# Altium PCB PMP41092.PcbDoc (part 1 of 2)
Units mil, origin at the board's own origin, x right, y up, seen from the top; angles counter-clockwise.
Board outline 1771.65 x 1771.65 mil, 6 copper layers (Top Layer 1, Layer 2, Layer 3, Layer 4, Layer 5, Bottom Layer), stack 32.112 mil thick; 119 components, 63 nets, 374 pads, 304 vias.
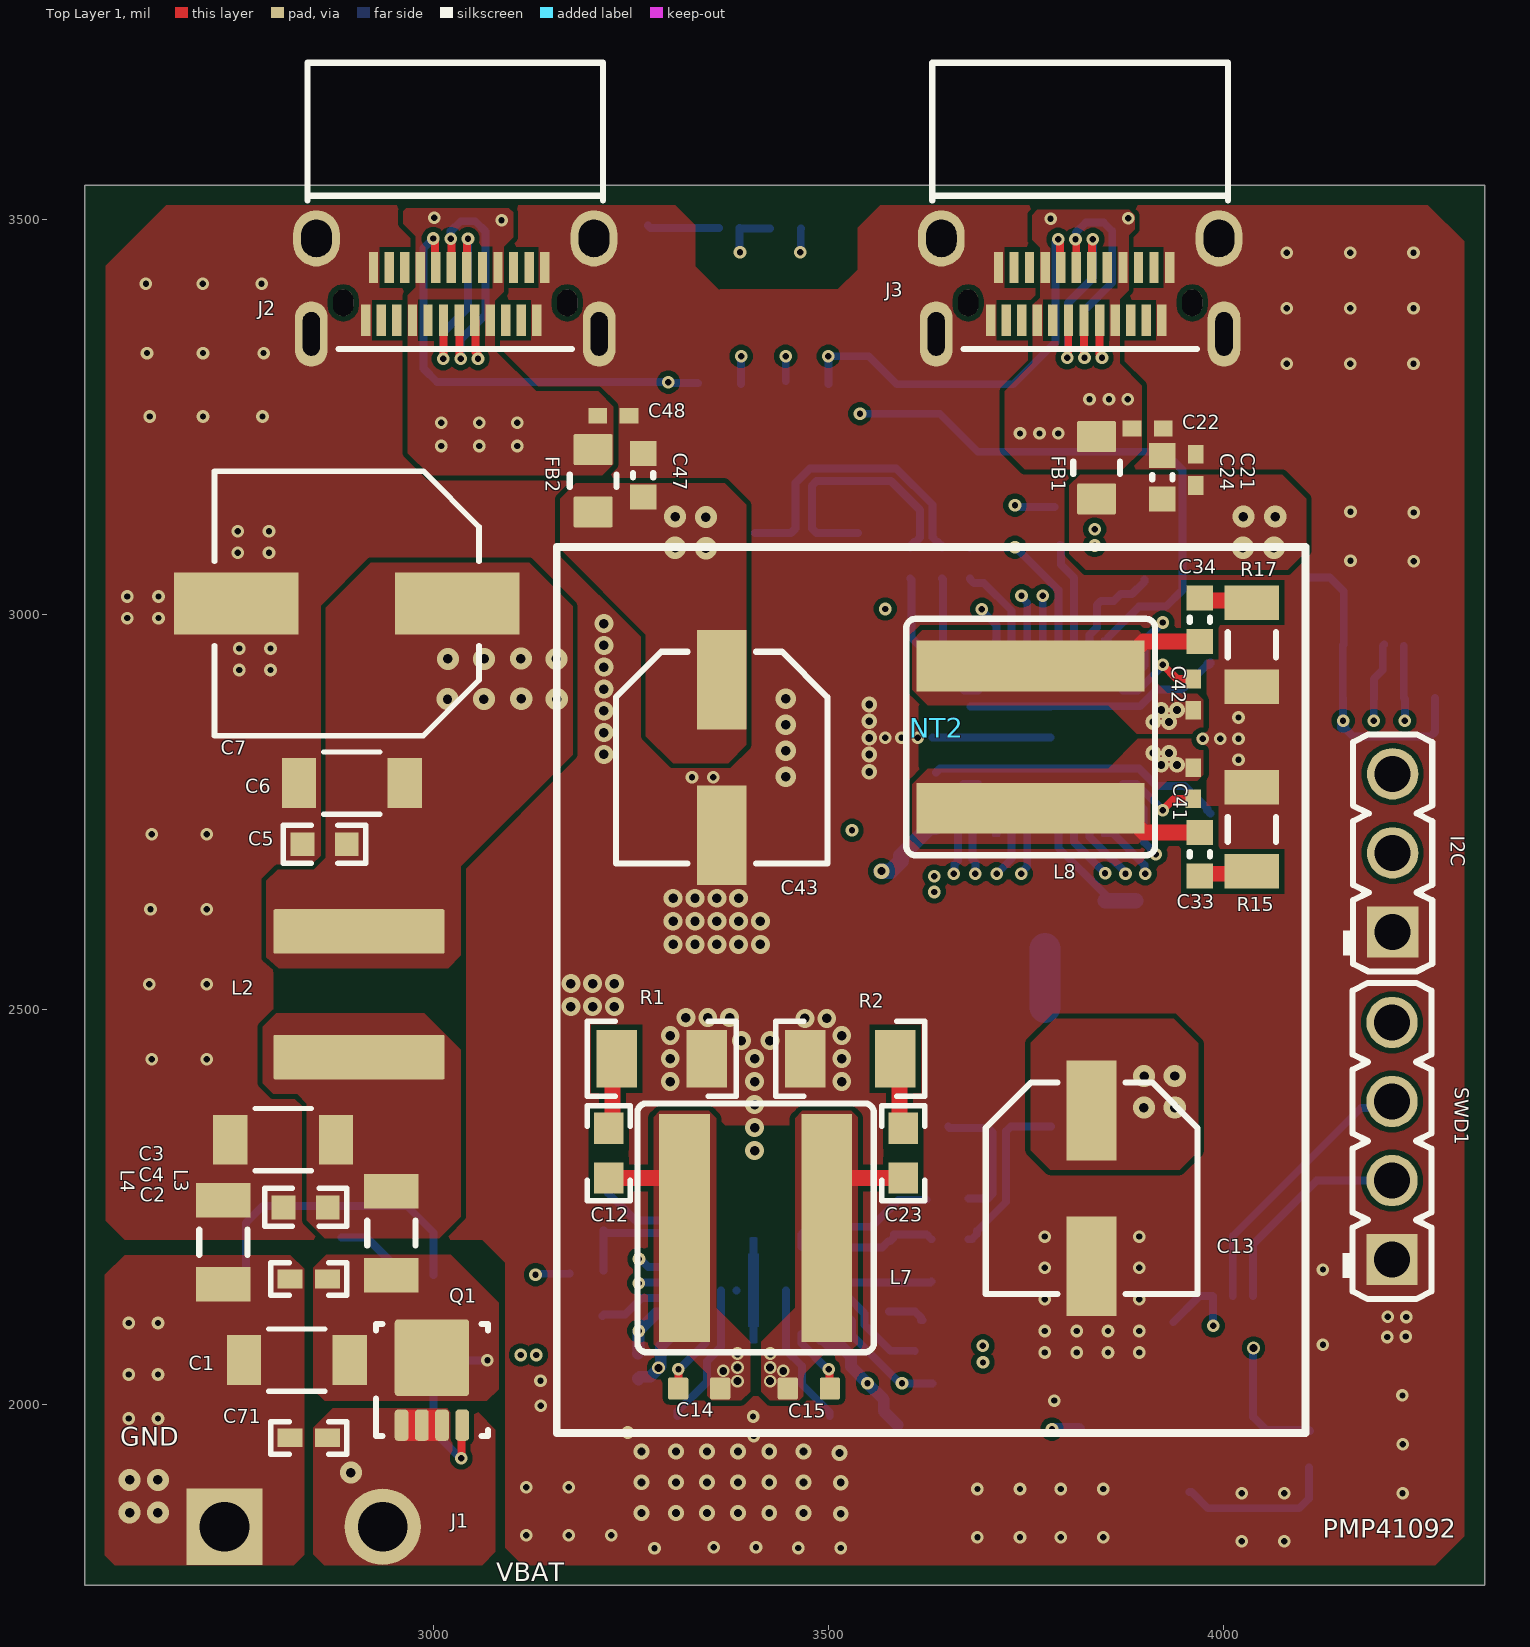
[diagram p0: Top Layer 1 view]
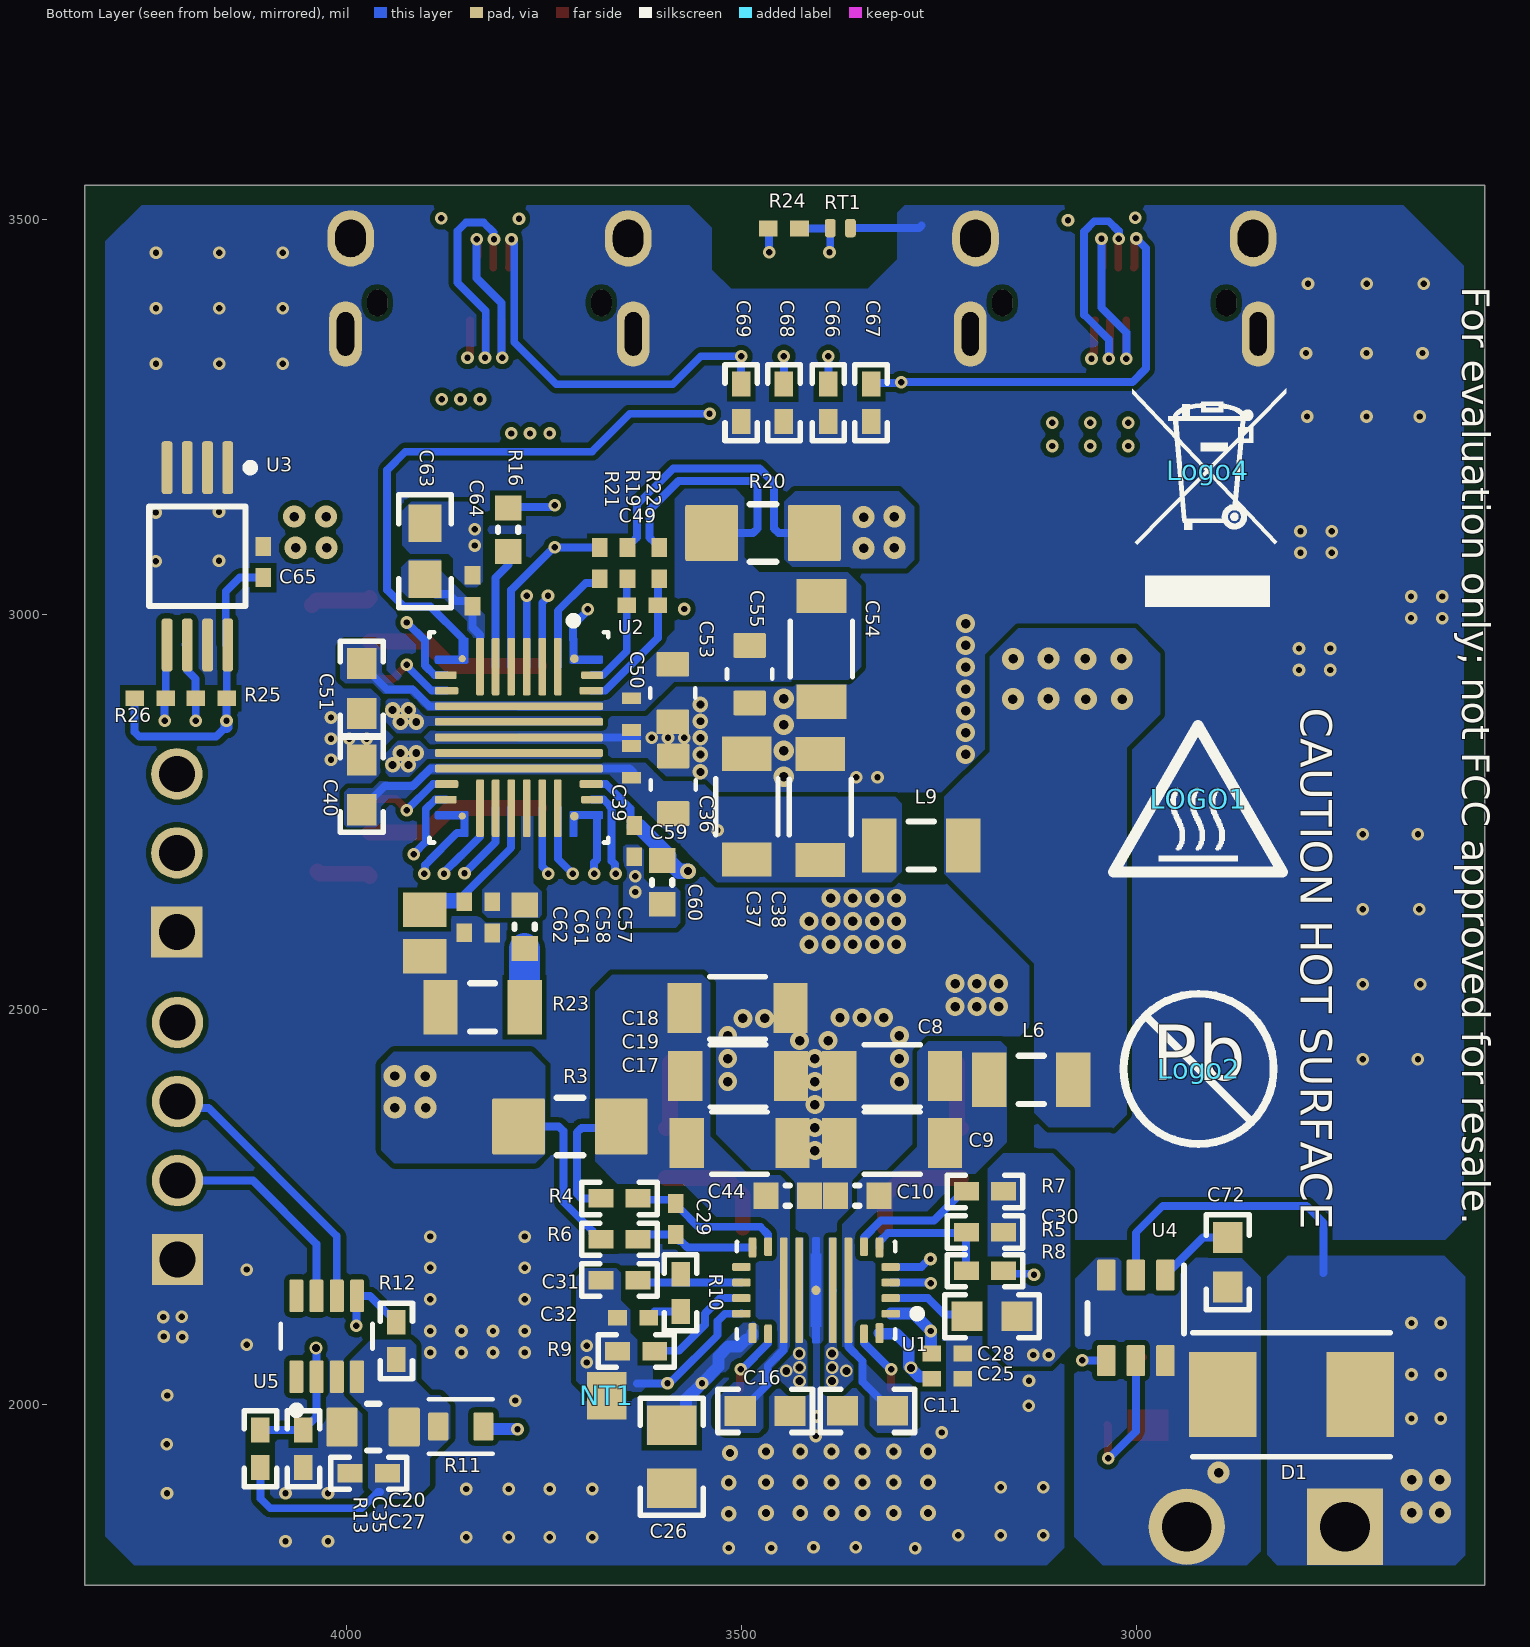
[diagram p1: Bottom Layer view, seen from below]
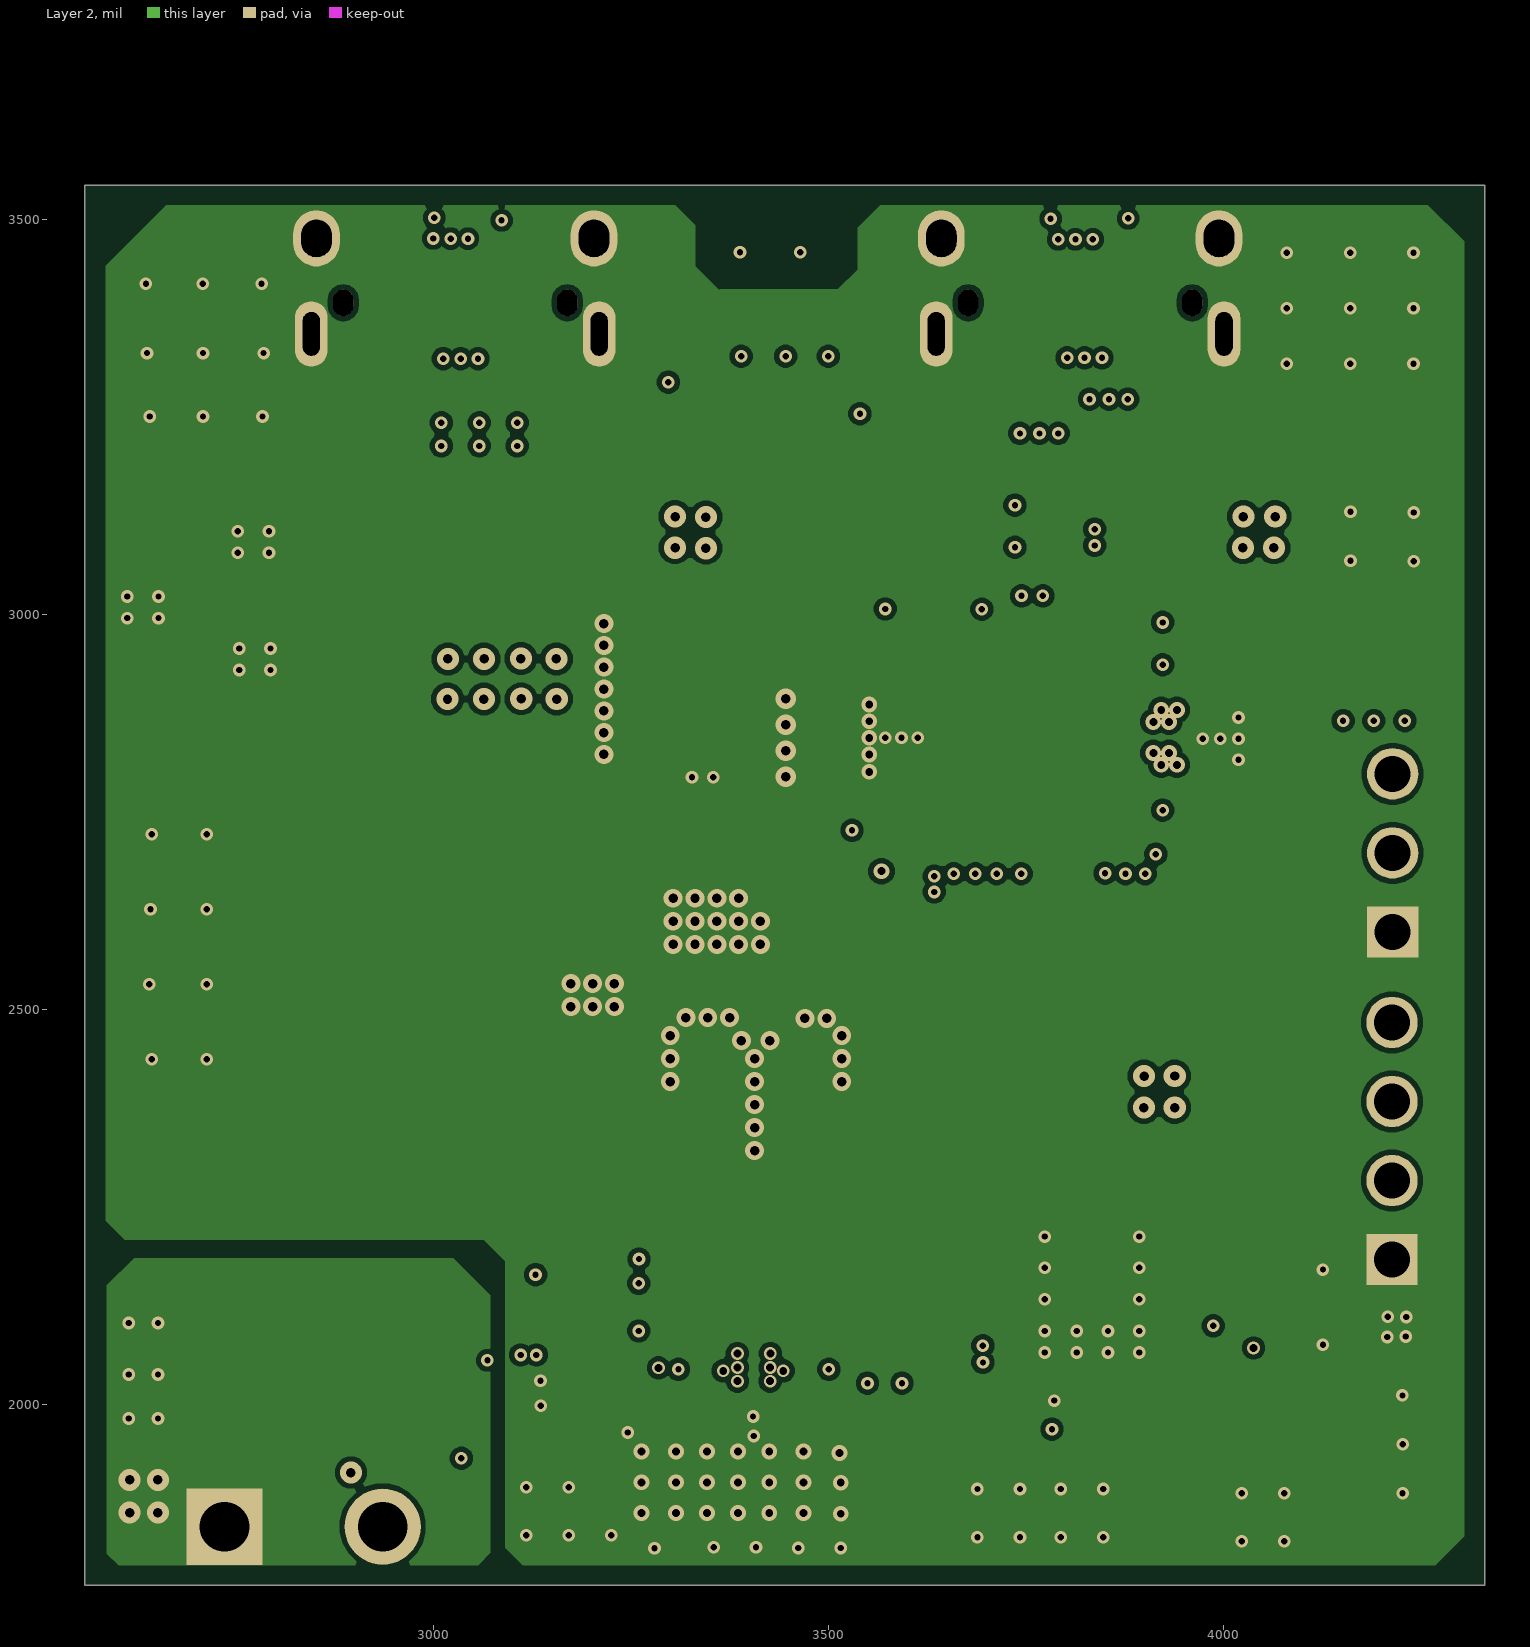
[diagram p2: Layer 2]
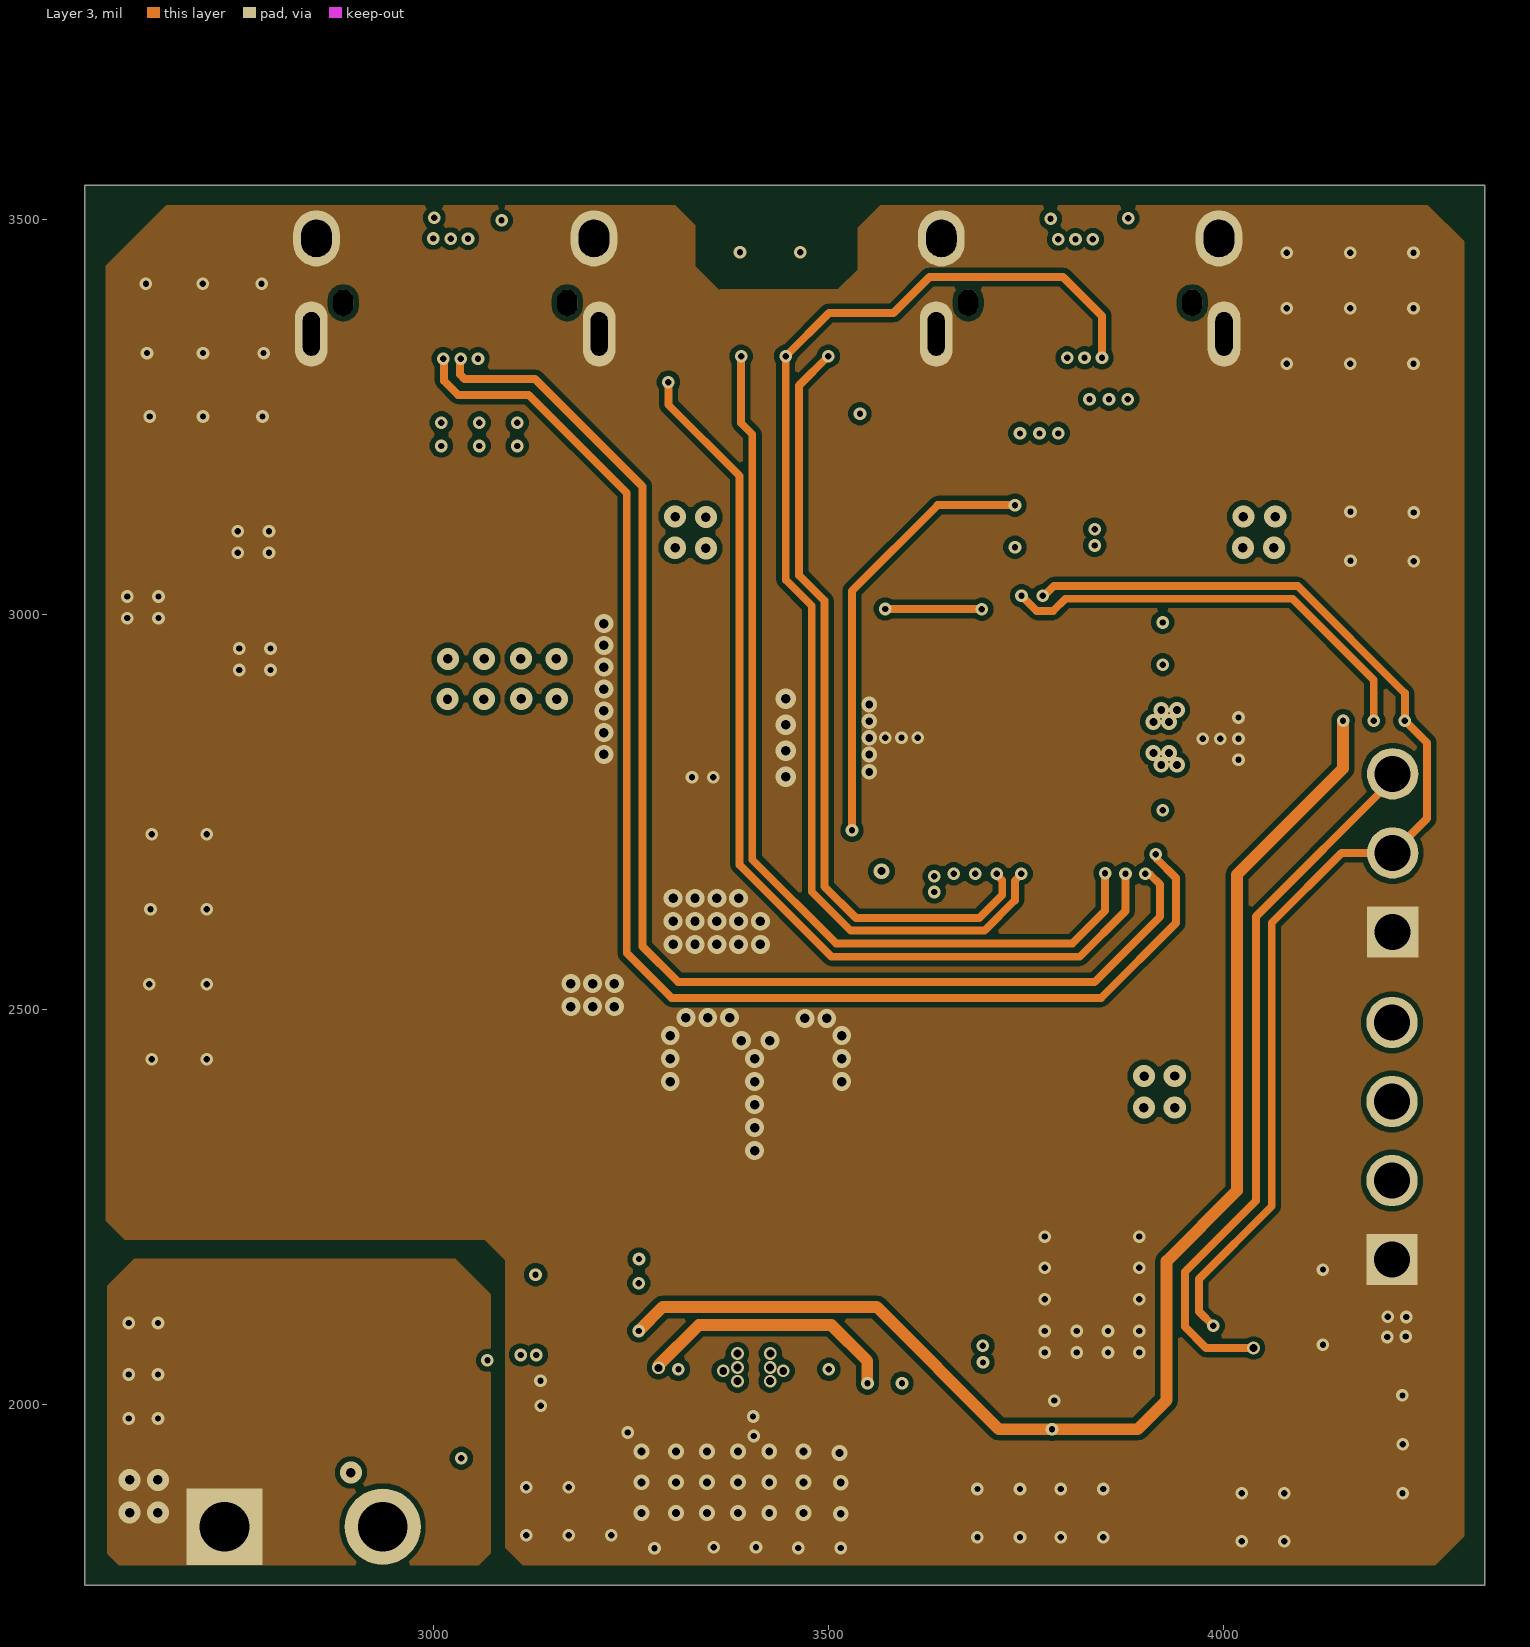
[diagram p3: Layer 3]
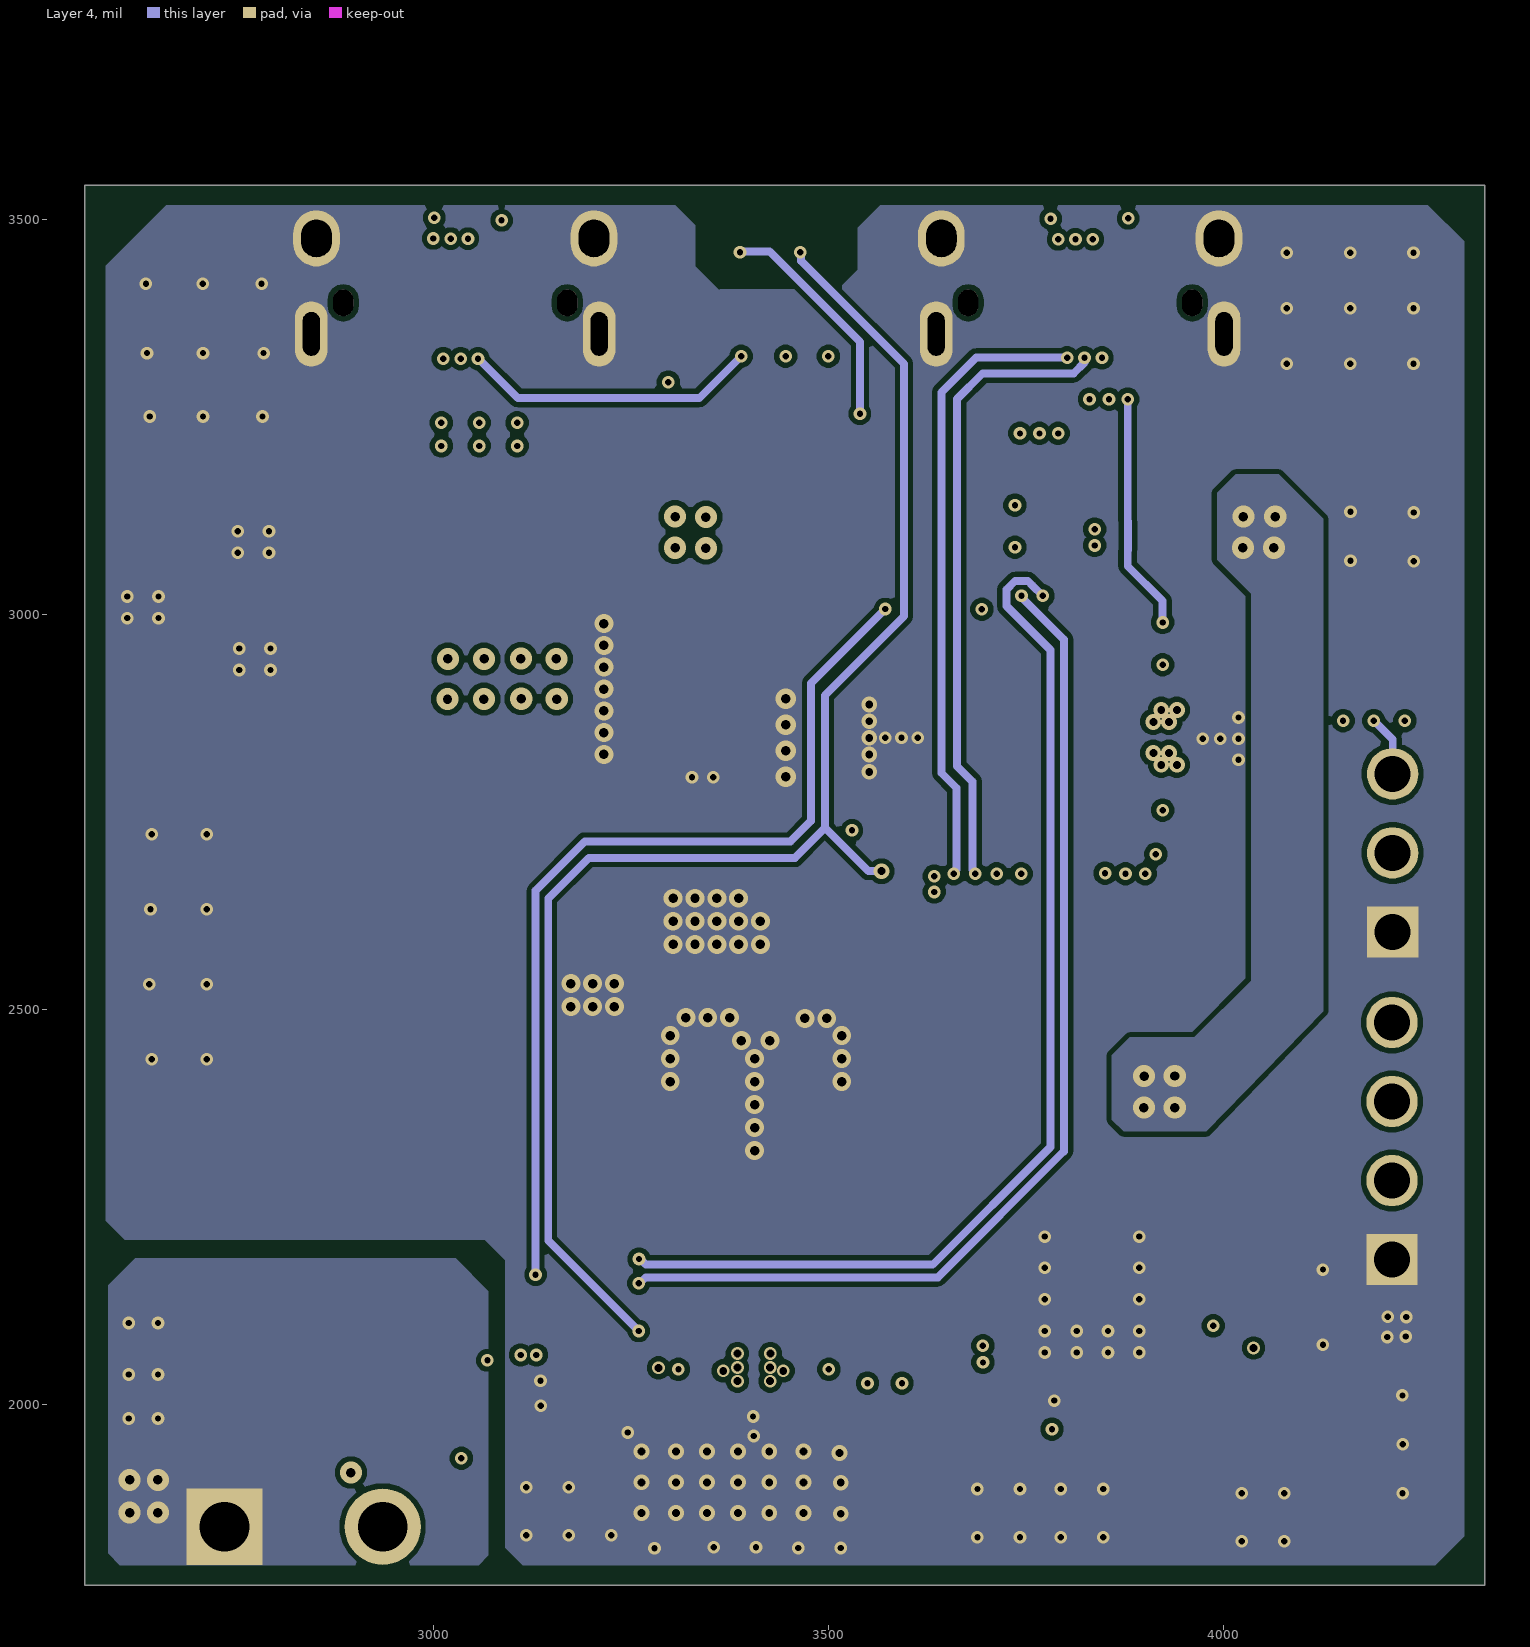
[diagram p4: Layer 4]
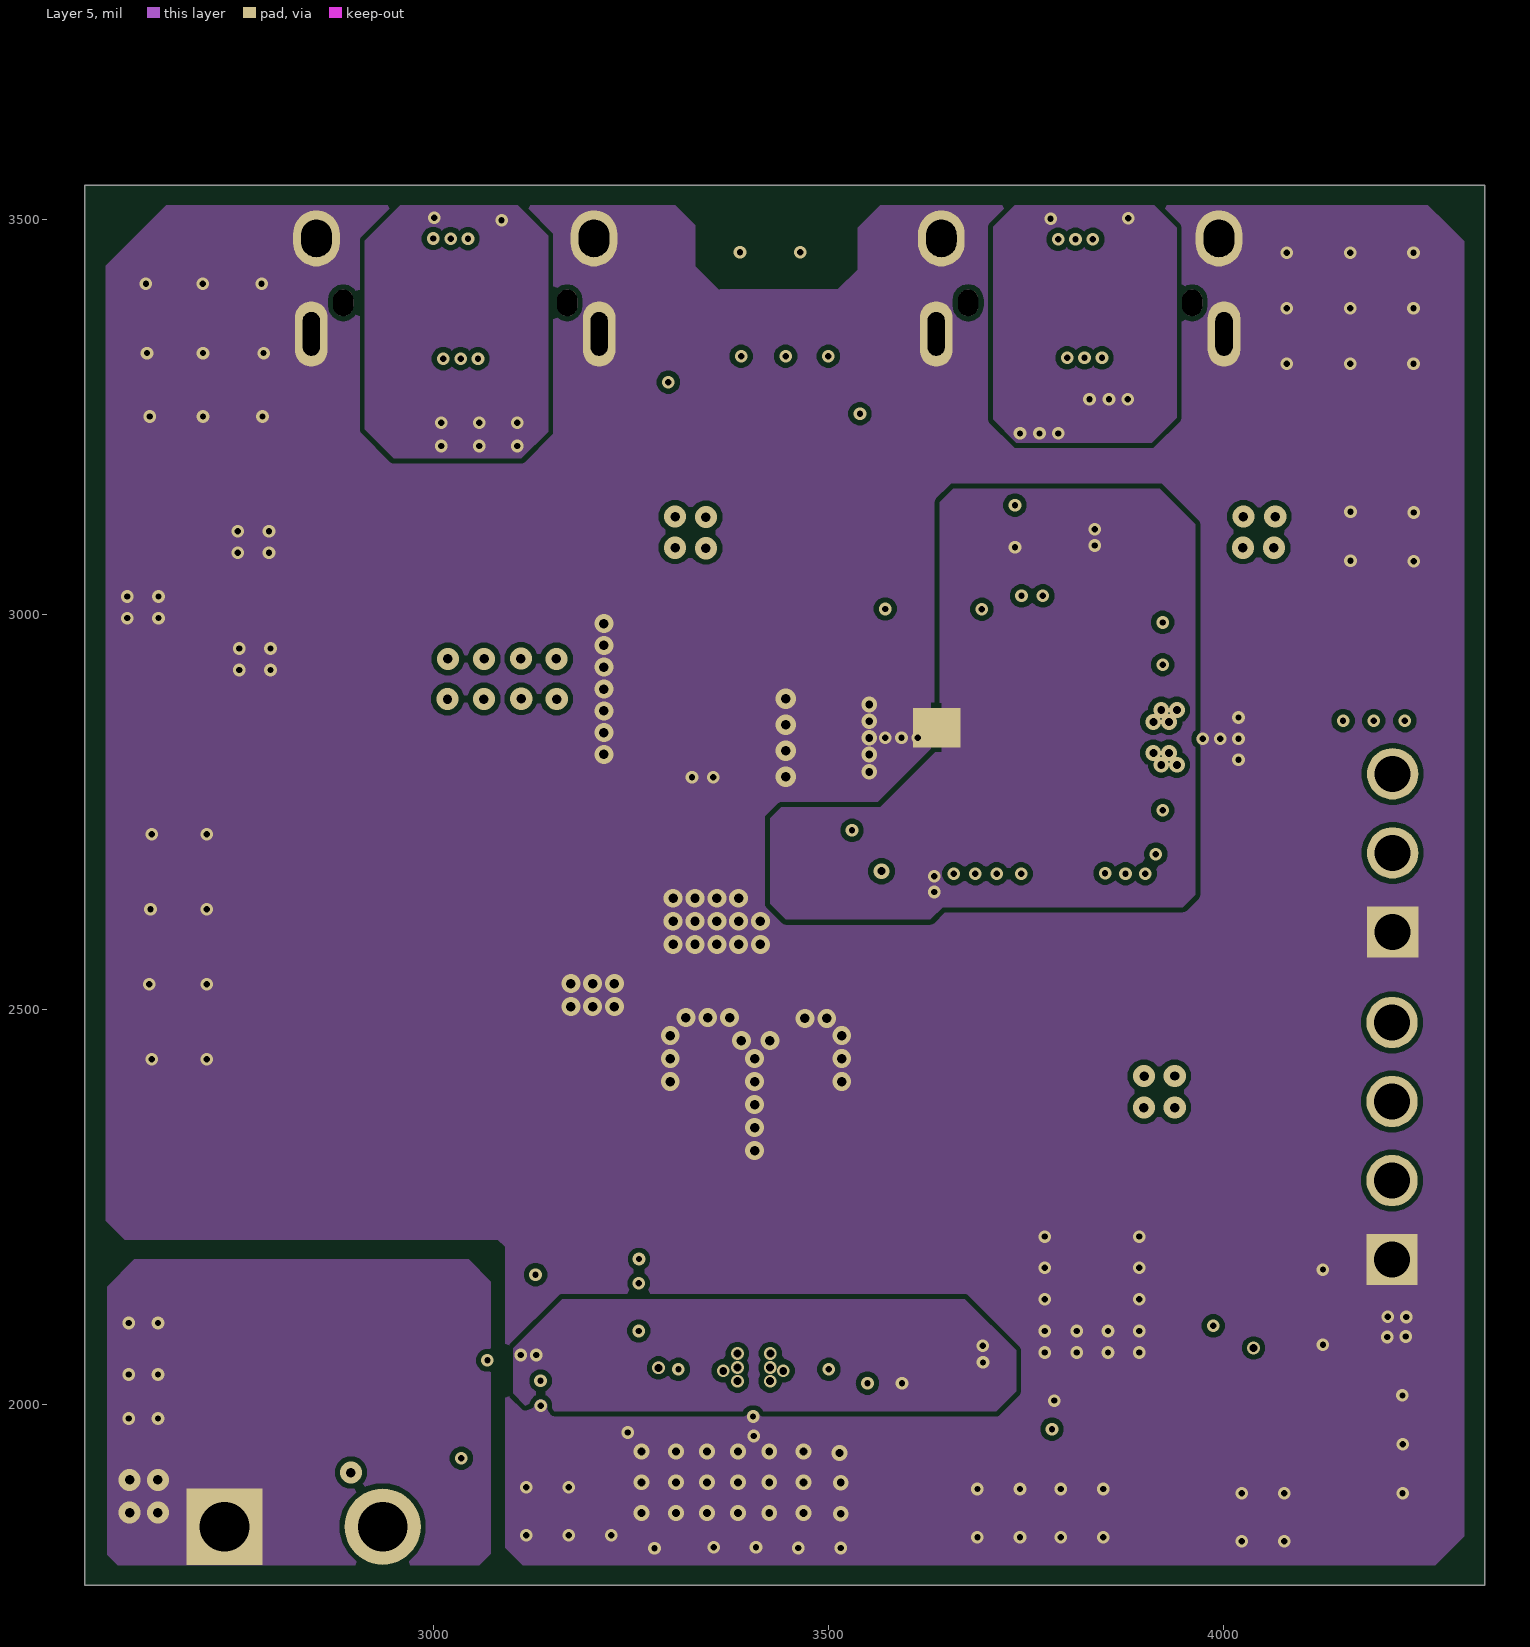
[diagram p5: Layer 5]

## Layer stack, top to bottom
Top Solder: solder mask 0.4, Solder Resist, Dk 3.5
Top Layer 1: signal copper 1.378
Dielectric 2: prepreg 2.8, PP-006, Dk 4.1
Layer 2: signal copper 1.4
Dielectric 4: prepreg 2.8, PP-006, Dk 4.1
Layer 3: signal copper 1.378
Dielectric 1: dielectric 12.6, FR-4, Dk 4.8
Layer 4: signal copper 1.378
Dielectric 5: prepreg 2.8, PP-006, Dk 4.1
Layer 5: signal copper 1.4
Dielectric 3: prepreg 2.8, PP-006, Dk 4.1
Bottom Layer: signal copper 1.378
Bottom Solder: solder mask 0.4, Solder Resist, Dk 3.5

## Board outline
2559.06,1771.65 4330.71,1771.65 4330.71,3543.31 2559.06,3543.31

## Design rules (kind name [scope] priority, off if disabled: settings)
AcuteAngle [All] p1: minimum=4.50000000000000E+0001 checktracksonly=FALSE
AssemblyTestPointUsage [All] p1: valid=2
BoardOutlineClearance BoardOutlineClearance_MountingHoles [OnCopper and InComponentClass('Mounting Holes')] p1: gap=10 ignorepadtopadclearanceinfootprint=FALSE
BoardOutlineClearance BoardOutlineClearance_Poly [OnCopper and IsPoly] p2: gap=25 ignorepadtopadclearanceinfootprint=FALSE
BoardOutlineClearance [OnCopper and Not InComponentClass('Logo') and not InComponentClass('FiducialMark') and not InRegion(1000,500,4000,800) and not InPoly] p3: gap=10 ignorepadtopadclearanceinfootprint=FALSE
Clearance Clearance_Keepouts [((IsTrack Or IsArc) And Not InPoly) And IsFree and IsKeepOut vs ((IsTrack Or IsArc) And Not InPoly) And IsFree and IsKeepOut] p1: gap=0 ignorepadtopadclearanceinfootprint=FALSE
Clearance Clearance_Poly [InPolygon] p2: gap=6.5 ignorepadtopadclearanceinfootprint=TRUE
Clearance Clearance_FiducialMark [IsKeepOut and InComponentClass('FiducialMark') vs IsPad and InComponentClass('FiducialMark')] p3: gap=0 ignorepadtopadclearanceinfootprint=FALSE
Clearance [All] p4: gap=6 ignorepadtopadclearanceinfootprint=TRUE
ComponentClearance ComponentClearance_MountingHoles_FiducialMarks [InComponentClass('Mounting Holes') vs InComponentClass('FiducialMark')] p1: gap=5 collisioncheckmode=3 verticalgap=3 showdistances=FALSE
ComponentClearance ComponentClearance_Shunt [InComponentClass('Header') vs InComponentClass('Shunt')] p2: gap=0 collisioncheckmode=3 verticalgap=0 showdistances=FALSE
ComponentClearance ComponentClearance_Logo [InComponentClass('Logo')] p3: gap=10 collisioncheckmode=3 verticalgap=10 showdistances=FALSE
ComponentClearance ComponentClearance_ScrewToNut [(HasFootprint('NY PMS 440 0025 PH')) vs (HasFootprint('Keystone_1902C'))] p4: gap=5 collisioncheckmode=3 verticalgap=10 showdistances=FALSE
ComponentClearance ComponentClearance_MountingHoles [InComponentClass('Mounting Holes')] p5: gap=50 collisioncheckmode=3 verticalgap=100000 showdistances=FALSE
ComponentClearance ComponentClearance_SmallPassives [HasFootprint('0201*') or HasFootprint('0402*') or HasFootprint('0508') or HasFootprint('0603*') or HasFootprint('0612') or HasFootprint('0805*') or HasFootprint('0815*') or HasFootprint('0830*') or HasFootprint('1206*') or HasFootprint('1210*') or HasFootprint('1808*') or HasFootprint('1812*') or HasFootprint('1825*') or HasFootprint('2010*') or HasFootprint('2220*') or HasFootprint('2225*') or HasFootprint('2512*') or HasFootprint('2728*') or HasFootprint('3518*') vs HasFootprint('0201*') or HasFootprint('0402*') or HasFootprint('0508') or HasFootprint('0603*') or HasFootprint('0612') or HasFootprint('0805*') or HasFootprint('0815*') or HasFootprint('0830*') or HasFootprint('1206*') or HasFootprint('1210*') or HasFootprint('1808*') or HasFootprint('1812*') or HasFootprint('1825*') or HasFootprint('2010*') or HasFootprint('2220*') or HasFootprint('2225*') or HasFootprint('2512*') or HasFootprint('2728*') or HasFootprint('3518*')] p6: gap=0 collisioncheckmode=3 verticalgap=0 showdistances=FALSE
ComponentClearance ComponentClearance_THtoSMT [IsThruComponent vs IsSMTComponent] p7: gap=2 collisioncheckmode=3 verticalgap=2 showdistances=FALSE
ComponentClearance ComponentClearance_THtoTH [IsThruComponent vs IsThruComponent] p8: gap=5 collisioncheckmode=3 verticalgap=5 showdistances=FALSE
ComponentClearance [All] p9: gap=0 collisioncheckmode=3 verticalgap=0 showdistances=FALSE
DiffPairsRouting [All] p1: maxlimit=15 minlimit=6 mostfreqgap=10 toplayer_minwidth=6 toplayer_maxwidth=15 toplayer_prefwidth=10 midlayer1_minwidth=6 midlayer1_maxwidth=15 midlayer1_prefwidth=10 midlayer2_minwidth=6 midlayer2_maxwidth=15 midlayer2_prefwidth=10 midlayer3_minwidth=6 midlayer3_maxwidth=15 midlayer3_prefwidth=10 midlayer4_minwidth=6 midlayer4_maxwidth=15 midlayer4_prefwidth=10 bottomlayer_minwidth=6 bottomlayer_maxwidth=15 bottomlayer_prefwidth=10 maxuncoupledlength=20
FabricationTestPointUsage TestPointUsage [All] p1: valid=2 allowmultiple=FALSE
FabricationTestpoint Testpoint [All] p1: side=3 testpointundercomponent=TRUE minsize=40 maxsize=100 preferedsize=60 minholesize=0 maxholesize=40 preferedholesize=32 testpointgrid=1 allowsidetop=TRUE allowsidebottom=TRUE usegrid=TRUE gridtolerance=0.01
FanoutControl Fanout_LCC [IsLCC] p1: bgadir=Out bgaviamode=Centered fanoutstyle=Auto fanoutdirection=Alternating viagrid=1 // Fanout_LCC (Default Rule)
FanoutControl Fanout_BGA [IsBGA] p2: bgadir=Out bgaviamode=Centered fanoutstyle=Auto fanoutdirection=Alternating viagrid=1 // Fanout_BGA (Default Rule)
FanoutControl Fanout_Default [All] p4: bgadir=Out bgaviamode=Centered fanoutstyle=Auto fanoutdirection=Alternating viagrid=1 // Fanout_Default (Default Rule)
FanoutControl Fanout_Small [(CompPinCount < 5)] p5: bgadir=Out bgaviamode=Centered fanoutstyle=Auto fanoutdirection=OutThenIn viagrid=1 // Fanout_Small (Default Rule)
HoleSize [All] p1: absolutevalues=TRUE maxlimit=300 minlimit=5 maxpercent=80.000 minpercent=20.000
HoleToHoleClearance [All] p1: gap=0 allowstackedmicrovias=TRUE
MatchedLengths DiffPair_MatchedLengths [InDifferentialPair ('PA_D')] p1: tolerance=1000 checknetsindiffpair=FALSE checkdiffpairvsdiffpair=TRUE checkxsignals=TRUE checkothers=TRUE
MatchedLengths [InDifferentialPair ('PA_D')] p2: tolerance=1000 checknetsindiffpair=FALSE checkdiffpairvsdiffpair=TRUE checkxsignals=TRUE checkothers=TRUE
MinimumAnnularRing MinimumAnnularRing_ThermalPadVias [IsVia and InAnyComponent] p1: minimumring=1.5
MinimumAnnularRing [All] p2: minimumring=1.5
MinimumSolderMaskSliver MinimumSolderMaskSliver_Logo [InComponentClass('Logo') vs InComponentClass('Logo')] p1: minsoldermaskwidth=0.7
MinimumSolderMaskSliver [All] p2: minsoldermaskwidth=0
PlaneConnect [All] p1: planeconnectstyle=Direct reliefexpansion=10 reliefentries=4 reliefconductorwidth=10 reliefairgap=10
PolygonConnect [All] p1: connectstyle=Direct reliefconductorwidth=10 reliefentries=4 polygonreliefangle="90 Angle" airgapwidth=10
RoomDefinition PMP41092_TPS55289 [InComponentClass('PMP41092_TPS55289')] p1: confinementstyle=ConfineIn formatcopy=TRUE lockcomponents=FALSE outline 0,0 2000,0 2000,1000 0,1000
RoomDefinition PMP41092_TPS25772 [InComponentClass('PMP41092_TPS25772')] p2: confinementstyle=ConfineIn formatcopy=TRUE lockcomponents=FALSE outline 0,0 2000,0 2000,1000 0,1000
RoomDefinition "PMP41092_Input filter" [InComponentClass('PMP41092_Input filter')] p3: confinementstyle=ConfineIn formatcopy=TRUE lockcomponents=FALSE outline 0,0 2000,0 2000,1000 0,1000
RoutingLayers [All] p1: top layer_v5=TRUE mid layer 1_v5=TRUE mid layer 2_v5=TRUE mid layer 3_v5=FALSE mid layer 4_v5=FALSE bottom layer_v5=TRUE
RoutingVias ThermalPadVias [IsVia and InAnyComponent] p1: holewidth=50 width=50 viastyle="Through Hole" minholewidth=5 minwidth=10 maxholewidth=100 maxwidth=200
RoutingVias [All] p2: holewidth=10 width=16 viastyle="Through Hole" minholewidth=6 minwidth=10 maxholewidth=100 maxwidth=300
ShortCircuit [All vs InNet('No Net')] p1: allowed=FALSE
SilkToSilkClearance SilkToSilkClearance_Pb-FreeLogo [(HasFootprint('Pb-Free_Overlay_Medium') OR HasFootprint('Pb-Free_Overlay_Small')) vs (HasFootprint('Pb-Free_Overlay_Medium') OR HasFootprint('Pb-Free_Overlay_Small'))] p1: silktosilkclearance=0
SilkToSilkClearance [All] p2: silktosilkclearance=0
SilkToSolderMaskClearance SilkToComponentPadClearance [(IsPad or IsFill or IsRegion) and InAnycomponent] p1: minsilkscreentomaskgap=0 clearancetoexposedcopper=TRUE
SilkToSolderMaskClearance "Silk to Solder Mask Opening" [All] p2: minsilkscreentomaskgap=0 clearancetoexposedcopper=FALSE
SolderMaskExpansion [All] p1: expansion=1.97 istentingtop=FALSE
UnRoutedNet [All] p1: checkbadconnections=TRUE
Width [All] p1: maxlimit=100 minlimit=6 preferedwidth=10 checkconnectedcopper=TRUE
12 further rules are at their usual default settings.

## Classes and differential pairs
component class PMP41092_TPS55289: C8 C9 C10 C11 C12 C13 C14 C15 C16 C17 C18 C19 C21 C22 C23 C24 C25 C26 C28 C29 C30 C31 C32 C44 FB1 L6 L7 LOGO1 Logo2 Logo3 Logo4 NT1 R1 R2 R3 R4 R5 R6 R7 R8 R9 R10 U1
component class PMP41092_TPS25772: C20 C27 C33 C34 C35 C36 C37 C38 C39 C40 C41 C42 C43 C47 C48 C49 C50 C51 C53 C54 C55 C57 C58 C59 C60 C61 C62 C63 C64 C65 C66 C67 C68 C69 FB2 I2C J2 J3 L8 L9 NT2 R11 R12 R13 R15 R16 R17 R19 R20 R21 R22 R23 R24 R25 R26 RT1 SWD1 U2 U3 U5 x
component class "PMP41092_Input filter": C1 C2 C3 C4 C5 C6 C7 C71 C72 D1 J1 L2 L3 L4 Q1 SH1 U4
differential pair PB_D: +PB_D_P -PB_D_N
differential pair PA_D: +PA_D_P -PA_D_N

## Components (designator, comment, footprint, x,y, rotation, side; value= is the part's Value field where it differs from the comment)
C1 "GRT31CD71H106KE13" 1206_190 2827.55,2056.62 r180 top value=10uF
C2 "Capacitor" 0402 2842.74,2159.27 r180 top value=0.1uF
C3 "CGA5L3X7R1H475K160AE" 1206_190 2810.31,2335.55 r180 top value=4.7uF
C4 "GRT155R71H472KE01" 0603_HV 2838.74,2249.83 r180 top value=4700pF
C5 "GRT155R71H472KE01" 0603_HV 2862.62,2709.18 r180 top value=4700pF
C6 "CGA5L3X7R1H475K160AE" 1206_190 2897.08,2786.73 r180 top value=4.7uF
C7 "EEE-FK1H101P" SM_RADIAL_F 2890.68,3014.01 r180 top value=100uF
C8 "CGA5L1X7R1H106K160AC" 1206_190 3308.91,2416.23 r0 bottom value=10uF
C9 "CGA5L1X7R1H106K160AC" 1206_190 3308.91,2331.18 r0 bottom value=10uF
C10 "CGA3E3X5R1H105M080AB" 0603L 3353.2,2264.69 r0 bottom value=1uF
C11 "GCM188R71H104KA57D" 0603 3340.11,1992.32 r0 bottom value=0.1uF
C12 "GRM1885C1H222JA01D" 0603 3222,2318.5 r270 top value=2200pF
C13 "GRM1885C1H222JA01D" 0603 3595,2318.5 r90 top value=2200pF
C14 "GCM188L81H104KA57D" FP-GCM188L81H104KA57D_0603-MFG 3336.59,2020.61 r0 top
C15 "GCM188L81H104KA57D" FP-GCM188L81H104KA57D_0603-MFG 3475.37,2020.61 r180 top
C16 "GCM188R71H104KA57D" 0603 3469.77,1992.26 r180 bottom value=0.1uF
C17 "GRT31CD71H106KE13" 1206_190 3502.09,2331.18 r180 bottom value=10uF
C18 "GRT31CD71H106KE13" 1206_190 3504.68,2502.14 r180 bottom value=10uF
C19 "GRT31CD71H106KE13" 1206_190 3504.01,2416.23 r180 bottom value=10uF
C20 "GCJ21BR71A106KE01L" 0805_HV1 3965.71,1971.87 r0 bottom value=10uF
C21 "Capacitor" 0402L 3964.88,3183 r90 top value=0.1uF
C22 "Capacitor" 0402L 3903.93,3235.36 r0 top value=0.1uF
C23 "EEHZK1V101XP" Panasonic_D 3833.12,2274.08 r270 top value=100uF
C24 "CGA3E3X5R1H105M080AB" 0603L 3922.58,3173.76 r90 top value=1uF
C25 "Capacitor" 0402L 3239.32,2033.17 r180 bottom value=0.1uF
C26 "GCM21BR71C475KA73K" 0805_HV 3587.9,1934.35 r270 bottom value=4.7uF
C27 "GRT155R71H104KE01" 0402 3971.13,1913.49 r180 bottom value=0.1uF
C28 "Capacitor" 0402L 3239.32,2065 r180 bottom value=0.1uF
C29 "CGA2B1X7R1V224K050BC" 0402L 3582.76,2235.16 r90 bottom value=0.22uF
C30 "CGA2B3X7R1H103K050BB" 0402 3191.52,2218.56 r180 bottom value=0.01uF
C31 "Capacitor" 0402 3653.97,2157.81 r0 bottom value=100pF
C32 "GCM155R71H472KA37D" 0402L 3636.81,2110.46 r0 bottom value=4700pF
C33 "GCM1885C1H102JA16D" 0603L 3970,2696.69 r270 top value=1000pF
C34 "GRM188R71H332KA01D" 0603L 3970,2993.31 r90 top value=3300pF
C35 "CGA2B3X7R1H103K050BB" 0402 4054.01,1944.52 r270 bottom value=0.01uF
C36 "GRT21BC71H475KE13" FP-CGA4J1X7R1H475K125AC_0805-MFG 3586,2784.58 r270 bottom value=4.7µF
C37 "GRT31CD71H106KE13" 1206_190 3492.89,2756.8 r90 bottom value=10uF
C38 "GRT31CD71H106KE13" 1206_190 3399.97,2756.51 r90 bottom value=10uF
C39 "GRT155R71H104KE01" 0402S 3639,2813.49 r270 bottom value=0.1uF
C40 "GCM188R71H104KA57D" 0603 3979.93,2784.54 r90 bottom value=0.1uF
C41 "GRT155R71H104KE01" 0402L 3961.99,2786.46 r90 top value=0.1uF
C42 "GRT155R71H104KE01" 0402L 3961.99,2898.69 r270 top value=0.1uF
C43 "EEHZK1V101XP" Panasonic_D 3365.05,2818.98 r270 top value=100uF
C44 "GCM188R71H104KA57D" 0603L 3441.31,2264.69 r180 bottom value=0.1uF
C47 "CGA3E3X5R1H105M080AB" 0603L 3265.82,3176.21 r90 top value=1uF
C48 "GRT155R71H104KE01" 0402L 3228.06,3251.38 r180 top value=0.1uF
C49 "CGA2B1X7R1V224K050BC" 0402L 3625.17,3011.76 r0 bottom value=0.22uF
C50 "GRT155R71H104KE01" 0402S 3639,2874 r90 bottom value=0.1uF
C51 "GCM188R71H104KA57D" 0603 3980,2906.5 r270 bottom value=0.1uF
C53 "GRT21BC71H475KE13" FP-CGA4J1X7R1H475K125AC_0805-MFG 3586.63,2900.72 r90 bottom value=4.7µF
C54 "GRT31CD71H106KE13" 1206_190 3398.58,2956.48 r270 bottom value=10uF
C55 "GRT21BC71H475KE13" FP-CGA4J1X7R1H475K125AC_0805-MFG 3489.35,2924.48 r90 bottom value=4.7µF
C57 "CGA3E3X7R1H474K080AE" 0603L 3774.02,2604.92 r270 bottom value=0.47uF
C58 "GRT155R71H104KE01" 0402L 3814.98,2616.73 r90 bottom value=0.1uF
C59 "GRT155R71C104KE01" 0402L 3635.11,2713.31 r270 bottom value=0.1uF
C60 "GRT188D70J106ME13D" 0603L 3600,2661 r270 bottom value=10uF
C61 "GRT155R71C104KE01" 0402L 3850.16,2617.08 r270 bottom value=0.1uF
C62 "GCM21BR71C475KA73K" 0805L 3900.61,2597.04 r270 bottom value=4.7uF
C63 "GRT188D70J106ME13D" 0603M 3900,3080 r90 bottom value=10uF
C64 "GRT155R71C104KE01" 0402L 3840,3030 r90 bottom value=0.1uF
C65 "GRT155R71H104KE01" 0402L 4104.8,3066.45 r270 bottom value=0.1uF
C66 "GRT155R71H331KE01" 0402 3389.89,3267.92 r270 bottom value=330pF
C67 "GRT155R71H331KE01" 0402 3335.66,3267.92 r270 bottom value=330pF
C68 "GRT155R71H331KE01" 0402 3446.08,3267.92 r270 bottom value=330pF
C69 "GRT155R71H331KE01" 0402 3500,3267.92 r270 bottom value=330pF
C71 "GRM155R71H104ME14D" 0402 2842.74,1958.25 r180 top value=0.1uF
C72 "GRM188R71E105KA12D" 0603 2884.24,2180.42 r270 bottom value=1uF
D1 "P6SMB33CA" SMB-Bi 2803.81,2013.05 r0 bottom value=28.2V
FB1 "BLM21SP700SZ1D" 0805_HV1 3839.37,3185.64 r90 top
FB2 "BLM21SP700SZ1D" 0805_HV1 3202.41,3169.24 r90 top
I2C "61300311121" WURTH_61300311121 4214,2698.35 r90 top
J1 "691313510002" FP-691313510002_TRM_BLK_HDR2-MFG 2836.16,1688.45 r0 top
J2 "632722200212" 632722200212 3027.91,3511.26 r180 top
J3 "632722200212" 632722200212 3818.6,3511.26 r180 top
L2 "XAL6060-472MEB" XAL6060 2906.3,2519.45 r90 top value=4.7uH
L3 "BLM31SN500SZ1L" 1206L 2947.25,2217.26 r90 top value="50 ohm"
L4 "BLM31SN500SZ1L" 1206L 2734.63,2205.82 r90 top value="50 ohm"
L6 "BLM31SN500SZ1L" 1206L 3133.08,2411.35 r0 bottom value="50 ohm"
L7 "XAL7070-472MEB" XAL7070 3408,2224 r0 top value=4.7uH
L8 "XAL7070-472MEB" XAL7070 3756,2845 r90 top value=4.7uH
L9 "BLM31SN500SZ1L" 1206L 3272.17,2707.78 r0 bottom value="50 ohm"
LOGO1 "CAUTION HOT SURFACE" IEC_HotSurface_Small 2922,2767 r180 bottom
Logo2 "Pb-Free Symbol" Pb-Free_Overlay_Medium 2921.26,2425.2 r180 bottom
Logo3 "FCC disclaimer" FCC_disclaimer 4657.47,2377.95 r90 bottom
Logo4 "WEEE logo" WEEE_Minimum 2910,3182 r180 bottom
NT1 "Net-Tie" Net-Tie_50milWide_30milLong#1 3670.01,2011.42 r270 bottom net-tie
NT2 "Net-Tie" Net-Tie_50milWide_30milLong#2 3637,2857 r0 top net-tie
Q1 "IPZ40N04S5L-2R8" PG-TSDSON-8-32 2998.45,2031.38 r90 top value=40V
R1 "Resistor" 1206 3289.29,2438 r0 top value=2.20
R2 "Resistor" 1206 3527.71,2438 r180 top value=2.20
R3 "CRF1206-FZ-R010ELF" FP-CRF1206-FZ-R010ELF_1206-MFG 3716.67,2352.25 r0 bottom
R4 "CRCW040210R0FKED" 0402 3653.97,2261.23 r180 bottom value=10.0
R5 "RK73Z1ETTP" 0402 3191.52,2169.68 r180 bottom value=0
R6 "CRCW040210R0FKED" 0402 3653.97,2209.56 r180 bottom value=10.0
R7 "Resistor" 0402 3191.52,2270.21 r0 bottom value=49.9k
R8 "ERJ-3GEY0R00V" 0603 3182.72,2112.29 r180 bottom value=0
R9 "Resistor" 0402 3633,2068 r180 bottom value=150k
R10 "CRCW040227K4FKED" 0402 3576.68,2141.72 r90 bottom value=27.4k
R11 "ERJ-3GEY0R00V" FP-ERJ-3GEY0R00V_0603-MFG 3854.74,1972.62 r0 bottom
R12 "RK73H1ETTP3301F" 0402 3936.37,2080.87 r270 bottom value=3.30k
R13 "RK73H1ETTP3301F" 0402 4108.41,1944.52 r270 bottom value=3.30k
R15 "CRCW12061R10FKEA" 1206L 4036,2728.19 r270 top value=1.10
R16 "CRCW060347K0FKEA" 0603L 3794.92,3107.26 r90 bottom value=47.0k
R17 "CRCW12061R10FKEA" 1206L 4036,2961.81 r270 top value=1.10
R19 "CRCW04020000Z0EDHP" 0402L 3643.84,3065.01 r90 bottom value=0
R20 "CRF1206-FZ-R010ELF" FP-CRF1206-FZ-R010ELF_1206-MFG 3472.41,3103.1 r180 bottom
R21 "CRCW040210R0FKED" 0402L 3603.71,3065.01 r90 bottom value=10.0
R22 "ERJ-2GEJ103X" 0402L 3679.22,3065.01 r270 bottom value=10k
R23 "RC1206FR-0710RL" 1206L 3827.15,2503 r180 bottom value=10.0
R24 "ERJ-2GEJ103X" 0402L 3445.94,3488.4 r0 bottom value=10k
R25 "RK73H1ETTP3301F" 0402L 4170.57,2893.91 r180 bottom value=3.30k
R26 "RK73H1ETTP3301F" 0402L 4247.79,2894.27 r0 bottom value=3.30k
RT1 "TMP6131QDECRQ1" DEC0002A 3374.56,3488.94 r0 bottom
SWD1 "61300411121" WURTH_61300411121 4213.24,2333.87 r90 top
U1 "TPS55289QWRYQRQ1" RYQ0021B-MFG 3405.33,2144.97 r0 bottom
U2 "TPS25772CQRQLRQ1" RQL0029A-MFG 3781.2,2844.51 r270 bottom
U3 "24LC256-I/ST" TSSOP-8 4188.05,3073.64 r270 bottom
U4 "LM74700QDBVRQ1" DBV0006A_N 3000.68,2110.07 r270 bottom
U5 "MSPM0C1104" DDF0008A-MFG 4024.49,2086.7 r90 bottom

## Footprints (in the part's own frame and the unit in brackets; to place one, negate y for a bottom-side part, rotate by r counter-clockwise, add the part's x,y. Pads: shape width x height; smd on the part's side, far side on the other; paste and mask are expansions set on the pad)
0402 [mm] "0402 from SM-752 data"
  rect 0.8x0.6 smd: 1(-0.6,0) 2(0.6,0)
  silkscreen extent -1.22,-0.52 1.22,0.52, body extent -0.55,-0.3 0.55,0.3, height 0.6
0402L [mm] "0402 from SM-752 data"
  rect 0.6x0.5 smd: 1(-0.5,0) 2(0.5,0)
  body extent -0.55,-0.3 0.55,0.3, height 0.6
0402S [mil] "Based on C0402S footprint from PADS legacy"
  rect 15x24 smd: 1(-20,0) 2(20,0)
  body extent -22,-12 22,12, height 24
0603 [mm] "0603 from SM-752 data"
  rect 1x0.95 smd: 1(-0.8,0) 2(0.8,0)
  silkscreen extent -1.52,-0.69 1.52,0.69, body extent -0.87,-0.47 0.87,0.47, height 1
0603_HV [mil] "Ernesto recommended land pattern.  26 mil between pads."
  rect 30x30 smd: 1(-28,0) 2(28,0)
  silkscreen extent -52,-24 52,24, body extent -34,-19 34,19, height 39
0603L [mm] "0603 from SM-752 data"
  rect 0.8x0.85 smd: 1(-0.7,0) 2(0.7,0)
  silkscreen extent -0.07,-0.33 0.07,0.33, body extent -0.87,-0.47 0.87,0.47, height 1
0603M [mm] "0603 from SM-752 data"
  rect 1.2x1.05 smd: 1(-0.9,0) 2(0.9,0)
  silkscreen extent -1.82,-0.84 1.82,0.84, body extent -0.87,-0.47 0.87,0.47, height 1
0805_HV [mil] "0805 with 30mil clearance between pads"
  rect 50x63 smd: 1(-40,0) 2(40,0)
  silkscreen extent -74,-40 74,40, body extent -43,-29 43,29, height 57
0805_HV1 [mm] "Custom footprint based on analyzing multiple manufacturer recommendations"
  rrect10% 1x1.25 smd: 1(-1,0) 2(1,0)
  silkscreen extent -0.2,-0.75 0.2,0.75, body extent -1.1,-0.72 1.1,0.73, height 1.45
0805L [mm] "0805 from SM-752 data"
  rect 1.1x1.4 smd: 1(-0.75,0) 2(0.75,0)
  body extent -1.1,-0.72 1.1,0.72, height 1.45
1206 [mm] "1206 from SM-752 data"
  rect 1.3x1.85 smd: 1(-1.45,0) 2(1.45,0)
  silkscreen extent -2.4,-1.21 2.4,1.21, body extent -1.7,-0.9 1.7,0.9, height 1.35
1206_190 [mm] "1206_190"
  rect 1.1x1.6 smd: 1(-1.7,0) 2(1.7,0)
  silkscreen extent -0.9,-1 0.9,1, body extent -1.75,-0.95 1.75,0.95, height 1.9
1206L [mm] "1206 from SM-752 data"
  rect 1.1x1.75 smd: 1(-1.35,0) 2(1.35,0)
  silkscreen extent -0.4,-0.77 0.4,0.77, body extent -1.7,-0.9 1.7,0.9, height 1.35
632722200212 [mm] "USB 3.1 Horizontal Receptacle SMT"
  rect 0.3x1 smd: A1(-2.625,3.53) A2(-2.125,3.53) A3(-1.625,3.53) A4(-1.125,3.53) A5(-0.625,3.53) A6(-0.125,3.53) A7(0.375,3.53) A8(0.875,3.53) A9(1.375,3.53) A10(1.875,3.53) A11(2.375,3.53) A12(2.875,3.53) B1(2.625,1.83) B2(2.125,1.83) B3(1.625,1.83) B4(1.125,1.83) B5(0.625,1.83) B6(0.125,1.83) B7(-0.375,1.83) B8(-0.875,1.83) B9(-1.375,1.83) B10(-1.875,1.83) B11(-2.375,1.83) B12(-2.875,1.83)
  oval 0.65x0.85 hole 0.65 slot 0.85 at 90 deg unplated: M1(-3.6,2.97) M2(3.6,2.97)
  oval 1.05x2.1 hole 0.55 slot 1.4 at 90 deg: Shell(-4.625,3.97) Shell(4.625,3.97)
  oval 1.5x1.8 hole 0.98 slot 1.2 at 90 deg: Shell(-4.46,0.9) Shell(4.46,0.9)
  silkscreen extent -4.75,-4.75 4.75,4.45, body extent -4.76,-4.75 4.75,4.45, height 5.51
DBV0006A_N [mm] "SOT23, 6-Leads, Body 2.9x1.6mm, Pitch 0.95mm, Lead Span 2.8mm, IPC Medium Density"
  rrect17% 1x0.6 smd: 1(-1.375,0.95) 2(-1.375,0) 3(-1.375,-0.95) 4(1.375,-0.95) 5(1.375,0) 6(1.375,0.95)
  silkscreen extent -1.68,-1.55 0.5,1.55, body extent -1.42,-1.46 1.42,1.46, height 1.12
DDF0008A-MFG [mm]
  rrect22% 1.05x0.45 smd paste+0 mask+0: 1(-1.3,0.975) 2(-1.3,0.325) 3(-1.3,-0.325) 4(-1.3,-0.975) 5(1.3,-0.975) 6(1.3,-0.325) 7(1.3,0.325) 8(1.3,0.975)
  silkscreen extent -2.5,-1.48 0.4,1.48, body extent -1.41,-1.45 1.41,1.45, height 1.1
DEC0002A [mm] "X1SON-2"
  rrect57% 0.35x0.6 smd paste-0.5 mask-0.05: 1(-0.325,0) 2(0.325,0)
  rrect33% 0.3x0.5 on Bottom Paste: 1S(-0.35,0) 2S(0.35,0)
  body extent -0.5,-0.3 0.5,0.3, height 0.5
FCC_disclaimer [mil]
FP-691313510002_TRM_BLK_HDR2-MFG [mm]
  rect 2.45x2.45 hole 1.6 paste-1000 mask+0: 1(-2.54,4)
  round 2.45 hole 1.6 paste-1000 mask+0: 2(2.54,4)
  body extent -6.25,-6.2 6.25,6.2, height 0.25
FP-CGA4J1X7R1H475K125AC_0805-MFG [mm]
  rrect13% 0.8x1.05 smd paste+0 mask+0: 1(-0.925,0) 2(0.925,0)
  silkscreen extent -0.15,-0.72 0.15,0.72, body extent -1,-0.63 1,0.63, height 1.45
FP-CRF1206-FZ-R010ELF_1206-MFG [mm]
  rrect6% 1.7x1.8 smd paste+0 mask+0: 1(-1.65,0) 2(1.65,0)
  silkscreen extent -0.43,-0.92 0.43,0.92, body extent -1.6,-0.82 1.6,0.82, height 0.8
FP-ERJ-3GEY0R00V_0603-MFG [mm]
  rrect15% 0.65x0.9 smd paste+0 mask+0: 1(-0.725,0) 2(0.725,0)
  silkscreen extent -1.03,-0.87 1.03,0.87, body extent -0.8,-0.4 0.8,0.4, height 0.55
FP-GCM188L81H104KA57D_0603-MFG [mm]
  rrect15% 0.65x0.7 smd paste+0 mask+0: 1(-0.675,0) 2(0.675,0)
  body extent -0.8,-0.4 0.8,0.4, height 0.9
IEC_HotSurface_Small [mil]
  silkscreen extent -107,-93 107,92
Net-Tie_50milWide_30milLong#1 [mil] "50mil net tie, no solder mask opening, no solder paste"
  rect 30x50 smd paste-20 mask-20: 1(-15,0) 2(15,0)
Net-Tie_50milWide_30milLong#2 [mil] "50mil net tie, no solder mask opening, no solder paste"
  rect 30x50 on Mid1 paste-20 mask-20: 1(-15,0) 2(15,0)
Panasonic_D [mm] "SMD, 2-Leads, Dia 6.3mm"
  rect 3.2x1.6 smd: 1(-2.5,0) 2(2.5,0)
  silkscreen extent -3.4,-3.4 3.4,3.4, body extent -3.4,-3.4 3.4,3.4, height 6.11
Pb-Free_Overlay_Medium [mil]
  silkscreen extent -95,-95 95,95
PG-TSDSON-8-32 [mm] "SMD, 8-Leads, Body 3.3x3.3mm"
  rrect45% 1x0.44 smd paste-1 mask-0.05: 1(-1.45,0.975) 2(-1.45,0.325) 3(-1.45,-0.325) 4(-1.45,-0.975) 5(1.45,-0.975) 6(1.45,-0.325) 7(1.45,0.325) 8(1.45,0.975)
  rrect6% 1.71x2.29 on Top Solder: 9(0.395,0)
  rrect8% 2.46x2.39 smd paste-2 mask-2: 9(0.72,0)
  rrect42% 0.3x0.24 on Top Paste: ""(-1.695,-0.325) ""(-1.695,0.325) ""(-1.695,0.975)
  rrect42% 0.7x0.24 on Top Paste: ""(-1.5,-0.975)
  rrect29% 0.35x0.67 on Top Paste: ""(-1.225,0.76) ""(-1.22,-0.11)
  rrect42% 1.4x0.24 on Top Paste: ""(0.35,0.975) ""(0.35,-0.975)
  rrect9% 1.4x1.09 on Top Paste: ""(0.35,0)
  rrect42% 0.6x0.24 on Top Paste: ""(1.55,-0.975) ""(1.55,-0.325) ""(1.55,0.325) ""(1.55,0.975)
  Top Layer 1 region: -1.95,-0.325 -0.95,-0.325 -0.95,1 -1.95,1
  silkscreen extent -1.8,-1.8 1.8,1.8, body extent -1.7,-1.7 1.7,1.7, height 1.15
RQL0029A-MFG [mm]
  round 0.278 smd paste+0 mask+0: 1(-2.53,1.78) 25(2.53,1.78)
  rrect40% 1.85x0.25 smd paste-1000 mask+0: 2(-2.275,1.25) 3(-2.275,0.75) 4(-2.275,0.25) 5(-2.275,-0.25) 6(-2.275,-0.75) 7(-2.275,-1.25) 19(2.275,-1.25) 20(2.275,-0.75) 21(2.275,-0.25) 22(2.275,0.25) 23(2.275,0.75) 24(2.275,1.25)
  round 0.229 smd paste+0 mask+0: 8(-2.53,-1.823) 18(2.53,-1.823)
  rrect40% 0.25x0.7 smd paste+0 mask+0: 9(-2,-2.35) 17(2,-2.35) 26(2,2.35) 29(-2,2.35)
  rrect40% 0.25x0.75 smd paste+0 mask+0: 10(-1.5,-2.325) 16(1.5,-2.325) 27(1.5,2.325) 28(-1.5,2.325)
  rrect40% 0.25x5.4 smd paste-1000 mask+0: 11(-1,0) 12(-0.5,0) 13(0,0) 14(0.5,0) 15(1,0)
  Top Layer 1 region: -2.425,-2.7 -2.575,-2.7 -2.594,-2.696 -2.61,-2.685 -2.621,-2.669 -2.625,-2.65 -2.625,-2.65 -2.625,-1.925 -2.629,-1.906 -2.64,-1.89 -2.656,-1.879 -2.675,-1.875 -2.675,-1.875 -3.15,-1.875 -3.175,-1.868 -3.193,-1.85 -3.2,-1.825 -3.2,-1.825 -3.2,-1.675 -3.196,-1.656 -3.185,-1.64 -3.169,-1.629 -3.15,-1.625 -3.15,-1.625 -2.425,-1.625 -2.406,-1.629 -2.39,-1.64 -2.379,-1.656 -2.375,-1.675 -2.375,-1.675 -2.375,-2.65 -2.379,-2.669 -2.39,-2.685 -2.406,-2.696 -2.425,-2.7
  Top Layer 1 region: 2.425,-2.7 2.575,-2.7 2.594,-2.696 2.61,-2.685 2.621,-2.669 2.625,-2.65 2.625,-2.65 2.625,-1.925 2.629,-1.906 2.64,-1.89 2.656,-1.879 2.675,-1.875 2.675,-1.875 3.15,-1.875 3.175,-1.868 3.193,-1.85 3.2,-1.825 3.2,-1.825 3.2,-1.675 3.196,-1.656 3.185,-1.64 3.169,-1.629 3.15,-1.625 3.15,-1.625 2.425,-1.625 2.406,-1.629 2.39,-1.64 2.379,-1.656 2.375,-1.675 2.375,-1.675 2.375,-2.65 2.379,-2.669 2.39,-2.685 2.406,-2.696 2.425,-2.7
  Top Layer 1 region: 2.425,2.7 2.575,2.7 2.594,2.696 2.61,2.685 2.621,2.669 2.625,2.65 2.625,2.65 2.625,1.925 2.629,1.906 2.64,1.89 2.656,1.879 2.675,1.875 2.675,1.875 3.15,1.875 3.175,1.868 3.193,1.85 3.2,1.825 3.2,1.825 3.2,1.675 3.196,1.656 3.185,1.64 3.169,1.629 3.15,1.625 3.15,1.625 2.425,1.625 2.406,1.629 2.39,1.64 2.379,1.656 2.375,1.675 2.375,1.675 2.375,2.65 2.379,2.669 2.39,2.685 2.406,2.696 2.425,2.7
  Top Layer 1 region: -2.425,2.7 -2.575,2.7 -2.594,2.696 -2.61,2.685 -2.621,2.669 -2.625,2.65 -2.625,2.65 -2.625,1.925 -2.629,1.906 -2.64,1.89 -2.656,1.879 -2.675,1.875 -2.675,1.875 -3.15,1.875 -3.169,1.871 -3.185,1.86 -3.196,1.844 -3.2,1.825 -3.2,1.825 -3.2,1.675 -3.196,1.656 -3.185,1.64 -3.169,1.629 -3.15,1.625 -3.15,1.625 -2.425,1.625 -2.406,1.629 -2.39,1.64 -2.379,1.656 -2.375,1.675 -2.375,1.675 -2.375,2.65 -2.379,2.669 -2.39,2.685 -2.406,2.696 -2.425,2.7
  silkscreen extent -3.87,-2.88 3.37,2.88, body extent -3,-2.5 3,2.5, height 1
RYQ0021B-MFG [mm]
  rrect40% 0.6x0.25 smd paste+0 mask+0: 1(-2.4,0.75) 2(-2.4,0.25) 3(-2.4,-0.25) 4(-2.4,-0.75) 14(2.4,-0.75) 15(2.4,-0.25) 16(2.4,0.25) 17(2.4,0.75)
  rrect40% 0.25x0.65 smd paste+0 mask+0: 5(-2.04,-1.375) 13(2.04,-1.375) 18(2.04,1.375) 21(-2.04,1.375)
  rrect40% 0.25x0.6 smd paste+0 mask+0: 6(-1.54,-1.4) 12(1.54,-1.4) 19(1.54,1.4) 20(-1.54,1.4)
  rrect40% 0.25x3.4 smd paste-1000 mask+0: 7(-1.04,0) 8(-0.54,0) 10(0.54,0) 11(1.04,0)
  round 0.297 smd paste-1000 mask+0: 9(0,0)
  Top Layer 1 region: -0.125,-1.65 -0.125,-1.175 -0.165,-1.175 -0.165,1.175 -0.125,1.175 -0.125,1.65 -0.118,1.675 -0.1,1.693 -0.075,1.7 -0.075,1.7 0.075,1.7 0.1,1.693 0.118,1.675 0.125,1.65 0.125,1.65 0.125,1.175 0.165,1.175 0.165,-1.175 0.125,-1.175 0.125,-1.65 0.118,-1.675 0.1,-1.693 0.075,-1.7 0.075,-1.7 -0.075,-1.7 -0.1,-1.693 -0.118,-1.675 -0.125,-1.65 -0.125,-1.65
  silkscreen extent -3.37,-1.55 2.55,1.55, body extent -2.5,-1.5 2.5,1.5, height 1
SM_RADIAL_F [mm] "8 x 10.2mm:  Panasonic F"
  rect 4x2 smd: 1(-3.55,0) 2(3.55,0)
  silkscreen extent -4.25,-4.25 4.25,4.25, body extent -4.25,-4.25 4.25,4.25, height 10.5
SMB-Bi [mil] "Molded Diode, 2-Leads, Body 5.4x3.6mm, IPC Medium Density, based on OnSemi component dimensions"
  rect 85x107.99 smd: 1(-87.01,0) 2(87.01,0)
  silkscreen extent -125,-79 125,79, body extent -104,-73 104,73, height 89
TSSOP-8 [mm] "TSSOP, 8-Leads, Body 3.1x4.5mm (max), Pitch 0.65mm, IPC Medium Density"
  rrect50% 1.7x0.35 smd: 1(-2.85,0.975) 2(-2.85,0.325) 3(-2.85,-0.325) 4(-2.85,-0.975) 5(2.85,-0.975) 6(2.85,-0.325) 7(2.85,0.325) 8(2.85,0.975)
  silkscreen extent -2.97,-1.55 1.6,1.82, body extent -3.2,-1.55 3.2,1.55, height 1.07
WEEE_Minimum [mil] "WEEElie bin"
  silkscreen extent -95,-172 99,104
WURTH_61300311121 [mm] "Header, 2.54mm, 3x1, TH"
  rect 1.65x1.65 hole 1.15: 1(-2.54,0)
  round 1.65 hole 1.15: 2(0,0) 3(2.54,0)
  silkscreen extent -3.81,-1.27 3.81,1.6, body extent -3.81,-1.27 3.81,1.27, height 8.54
WURTH_61300411121 [mm] "Header, 2.54mm, 4x1, TH"
  rect 1.65x1.65 hole 1.15: 1(-3.81,0)
  round 1.65 hole 1.15: 2(-1.27,0) 3(1.27,0) 4(3.81,0)
  silkscreen extent -5.08,-1.27 5.08,1.6, body extent -5.08,-1.27 5.08,1.27, height 8.54
XAL6060 [mm] "Coilcraft recommended land pattern Document 887-4 Revised 01/14/18"
  rrect7% 1.43x5.5 smd: 1(-2.019,0) 2(2.019,0)
  body extent -3.28,-3.38 3.28,3.38, height 6.11
XAL7070 [mm] "COILCRAFT"
  rect 1.63x7.33 smd: 1(-2.285,0) 2(2.285,0)
  silkscreen extent -3.8,-4 3.8,4, body extent -3.8,-4 3.8,4, height 7

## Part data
C1 C17 C18 C19 C37 C38 C54: library part CMP-0008808-1, "CAP, CERM, 10 µF, 50 V,+/- 10%, X7R, AEC-Q200 Grade 1, 1206", Cap_Case=1206, Manufacturer=MuRata, TempCo=X7T, Tolerance_%=10%, Value1=Unknown, Value2=50V, ValueDisplayed=10uF
C2 C21 C22 C25 C28: library part CMP-0006325-2, "CAP, CERM, 0.1 uF, 50 V, +/- 10%, X7R, AEC-Q200 Grade 1, 0402", Cap_Case=0402, Manufacturer=MuRata, PartNumber=GRT155R71H104KE01, Supplier Part Number 1=445-6899-1-ND, TempCo=X7R, Tolerance_%=10%, Value1="0.039064 ohm", Value2=50V, ValueDisplayed=0.1uF
C3 C6: library part CMP-0085349-1, "CAP, CERM, 4.7 µF, 50 V,+/- 10%, X7R, AEC-Q200 Grade 1, 1206", Cap_Case=1206, Manufacturer=TDK, TempCo=X7R, Tolerance_%=10%, Value2=50V, ValueDisplayed=4.7µF
C4 C5: library part CMP-0007146-1, "CAP, CERM, 4700 pF, 50 V, +/- 10%, X7R, AEC-Q200 Grade 1, 0603", Cap_Case=0603, Manufacturer=MuRata, Supplier Part Number 1=490-4932-1-ND, TempCo=X7R, Tolerance_%=10%, Value1=Unknown, Value2=50V, ValueDisplayed=4700pF
C7: library part CMP-0011177-2, "CAP, AL, 100 uF, 50 V, +/- 20%, 0.34 ohm, AEC-Q200 Grade 2, SMD", Cap_Case=F, Manufacturer=Panasonic, Supplier Part Number 1=PCE3809CT-ND, Tolerance_%=20%, Value1="0.34 ohm", Value2=50V, ValueDisplayed=100uF
C8 C9: library part CMP-0085950-1, "CAP, CERM, 10 µF, 50 V,+/- 10%, X7R, AEC-Q200 Grade 1, 1206", Cap_Case=1206, Manufacturer=TDK, TempCo=X7R, Tolerance_%=10%, Value2=50V, ValueDisplayed=10µF
C10 C24 C47: library part CMP-0083707-1, "CAP, CERM, 1 µF, 50 V,+/- 20%, X5R, AEC-Q200 Grade 3, 0603", Cap_Case=0603, Manufacturer=TDK, Supplier Part Number 1=445-12510-1-ND, TempCo=X5R, Tolerance_%=20%, Value2=50V, ValueDisplayed=1µF
C11 C16 C40 C44 C51: library part CMP-0007144-3, "CAP, CERM, 0.1 uF, 50 V, +/- 10%, X7R, 0603", Cap_Case=0603, Manufacturer=MuRata, Supplier Part Number 1=490-4779-1-ND, TempCo=X7R, Tolerance_%=10%, Value1="0.02 ohm", Value2=50V, ValueDisplayed=0.1uF
C12 C13: library part CMP-0007198-4, "CAP, CERM, 2200 pF, 50 V, +/- 5%, C0G/NP0, 0603", Cap_Case=0603, Manufacturer=MuRata, Supplier Part Number 1=490-1459-1-ND, TempCo=C0G/NP0, Tolerance_%=5%, Value1=Unknown, Value2=50V, ValueDisplayed=2200pF
C14 C15: library part CMP-0086535-1, "0.1µF ±10% 50V Ceramic Capacitor X8L 0603 (1608 Metric)", Manufacturer="Murata Electronics North America", TempCo=-40+15%, Tolerance_%=0.1
C20: library part CMP-0079153-1, "CAP, CERM, 10 µF, 10 V,+/- 10%, X7R, AEC-Q200 Grade 1, 0805", Cap_Case=0805, Manufacturer=MuRata, Supplier Part Number 1=490-12646-1-ND, TempCo=X7R, Tolerance_%=10%, Value2=10V, ValueDisplayed=10µF
C23 C43: library part CMP-0010737-1, "CAP, AL, 100 uF, 35 V, AEC-Q200 Grade 2, SMD", Cap_Case=6.3x7.7mm, Manufacturer=Panasonic, Supplier Part Number 1=PCE5016CT-ND, Tolerance_%=20%, Value1="0.26 ohm", Value2=35V, ValueDisplayed=100uF
C26 C62: library part CMP-0008019-1, "CAP, CERM, 4.7 uF, 16 V, +/- 10%, X7R, AEC-Q200 Grade 1, 0805", Cap_Case=0805, Manufacturer=MuRata, Supplier Part Number 1=GCM21BR71C475KA73K-ND, TempCo=X7R, Tolerance_%=10%, Value1=Unknown, Value2=16V, ValueDisplayed=4.7uF
C27 C41 C42 C65: library part CMP-0006325-2, "CAP, CERM, 0.1 uF, 50 V, +/- 10%, X7R, AEC-Q200 Grade 1, 0402", Cap_Case=0402, Manufacturer=MuRata, Supplier Part Number 1=445-6899-1-ND, TempCo=X7R, Tolerance_%=10%, Value1="0.039064 ohm", Value2=50V, ValueDisplayed=0.1uF
C29 C49: library part CMP-0006325-2, "CAP, CERM, 0.22 uF, 35 V, +/- 10%, X7R, AEC-Q200 Grade 1, 0402", Cap_Case=0402, Manufacturer=TDK, Supplier Part Number 1=445-6899-1-ND, TempCo=X7R, Tolerance_%=10%, Value1="0.039064 ohm", Value2=50V, ValueDisplayed=0.22uF
C30 C35: library part CMP-0006324-2, "CAP, CERM, 0.01 uF, 50 V, +/- 10%, X7R, AEC-Q200 Grade 1, 0402", Cap_Case=0402, Manufacturer=TDK, Supplier Part Number 1=445-6893-1-ND, TempCo=X7R, Tolerance_%=10%, Value1="0.333065 ohm", Value2=50V, ValueDisplayed=0.01uF
C31: library part CMP-0006308-2, "CAP, CERM, 100 pF, 50 V, +/- 5%, C0G/NP0, AEC-Q200 Grade 1, 0402", Cap_Case=0402, Manufacturer=TDK, PartNumber=CGA2B2C0G1H101J050BA, Supplier Part Number 1=445-5596-1-ND, TempCo=C0G/NP0, Tolerance_%=5%, Value1=Unknown, Value2=50V, ValueDisplayed=100pF
C32: library part CMP-0006361-1, "CAP, CERM, 4700 pF, 50 V, +/- 10%, X7R, AEC-Q200 Grade 1, 0402", Cap_Case=0402, Manufacturer=MuRata, Supplier Part Number 1=490-4915-1-ND, TempCo=X7R, Tolerance_%=10%, Value1=Unknown, Value2=50V, ValueDisplayed=4700pF
C33: library part CMP-0086079-1, "CAP, CERM, 1000 pF, 50 V,+/- 5%, C0G/NP0, AEC-Q200 Grade 1, 0603", Cap_Case=0603, Manufacturer=MuRata, TempCo=C0G/NP0, Tolerance_%=5%, Value2=50V, ValueDisplayed=1000pF
C34: library part CMP-0007450-4, "CAP, CERM, 3300 pF, 50 V, +/- 10%, X7R, 0603", Cap_Case=0603, Manufacturer=MuRata, Supplier Part Number 1=490-1503-1-ND, TempCo=X7R, Tolerance_%=10%, Value1=Unknown, Value2=50V, ValueDisplayed=3300pF
C36 C53 C55: library part CMP-0090082-1, "Cap Ceramic 4.7uF 50V X7R 10% Pad SMD 0805 +125°C Automotive T/R", Manufacturer=MuRata, Operating Temperature Range="-55°C to +125°C", TempCo=15%, Temperature Characteristic=X7R, Tolerance_%=0.1%, ValueDisplayed=4.7uF
C39 C48 C50 C58: library part CMP-0006325-2, "CAP, CERM, 0.1 uF, 50 V, +/- 10%, X7R, AEC-Q200 Grade 1, 0402", Cap_Case=0402, Manufacturer=Murata, Supplier Part Number 1=445-6899-1-ND, TempCo=X7R, Tolerance_%=10%, Value1="0.039064 ohm", Value2=50V, ValueDisplayed=0.1uF
C57: library part CMP-0007097-2, "CAP, CERM, 0.47 uF, 50 V, +/- 10%, X7R, AEC-Q200 Grade 1, 0603", Cap_Case=0603, Manufacturer=TDK, Supplier Part Number 1=445-172475-1-ND, TempCo=X7R, Tolerance_%=10%, Value1=Unknown, Value2=50V, ValueDisplayed=0.47uF
C59 C61 C64: library part CMP-0006201-2, "CAP, CERM, 0.1 uF, 16 V, +/- 10%, X7R, 0402", Cap_Case=0402, Manufacturer=MuRata, Supplier Part Number 1=478-7888-1-ND, TempCo=X7R, Tolerance_%=10%, Value1=Unknown, Value2=16V, ValueDisplayed=0.1uF
C60 C63: library part CMP-0007288-3, "CAP, CERM, 10 uF, 6.3 V, +/- 10%, B, 0603", Cap_Case=0603, Manufacturer=MuRata, TempCo=B, Tolerance_%=10%, Value1=Unknown, Value2=6.3V, ValueDisplayed=10uF
C66 C67 C68 C69: library part CMP-0006687-2, "CAP, CERM, 330 pF, 50 V, +/- 10%, X7R, 0402", Cap_Case=0402, Manufacturer=MuRata, Supplier Part Number 1=490-3247-1-ND, TempCo=X7R, Tolerance_%=10%, Value1=Unknown, Value2=50V, ValueDisplayed=330pF
C71: library part CMP-0006675-2, "CAP, CERM, 0.1 uF, 50 V, +/- 20%, X7R, 0402", Cap_Case=0402, Manufacturer=MuRata, Supplier Part Number 1=490-10701-1-ND, TempCo=X7R, Tolerance_%=20%, Value1=Unknown, Value2=50V, ValueDisplayed=0.1uF
C72: library part CMP-0007405-4, "CAP, CERM, 1 uF, 25 V, +/- 10%, X7R, 0603", Cap_Case=0603, Manufacturer=MuRata, Supplier Part Number 1=490-5307-1-ND, TempCo=X7R, Tolerance_%=10%, Value1=Unknown, Value2=25V, ValueDisplayed=1uF
D1: library part CMP-0079633-1, "Diode, TVS, Bi, 28.2 V, 45.7 Vc, SMB", Manufacturer=Littelfuse, Supplier Part Number 1=P6SMB33CALFCT-ND
FB1 FB2: library part CMP-0091807-2, "Chip Ferrite Bead, 0805, 70Ω @ 100MHz, 0.009Ω, 25%, 6A", Impedance At Frequency="70Ω @ 100MHz", Manufacturer=Murata, Operating Temperature Range="-55°C to +125°C", Test Frequency=100MHz, Tolerance_%=0.25%
I2C: library part CMP-0054796-1, "Header, 2.54 mm, 3x1, Gold, TH", Manufacturer="Wurth Elektronik", Supplier Part Number 1=732-5316-ND
J1: library part CMP-0074821-1, "TERM BLK HDR 5.08MM HORZ PCB 2P", Current_A=20A, Manufacturer="Wurth Electronics", Voltage_V=300V
J2 J3: library part CMP-03913-134708306-1, "632722200212 WR-COM_USB 3.1_Type C_Horizontal_SMT", Current Rating=5A, Insulation Resistance=1GΩ, Max Operating Temperature=120°C, Min Operating Temperature=-40°C
L2: library part CMP-0061020-2, "Inductor, Shielded, Composite, 4.7 µH, 10.5 A, 0.0144 ohm, AEC-Q200 Grade 1, SMD", Manufacturer=Coilcraft, Value1="0.0144 ohm", Value2=10.5A, ValueDisplayed=4.7uH
L3 L4 L6 L9: library part CMP-0003368-1, "Ferrite Bead, 50 ohm @ 100 MHz, 12 A, 1206", Manufacturer=MuRata, Supplier Part Number 1=490-13270-1-ND, Value1="0.0016 ohm", Value2=12A, ValueDisplayed="50 ohm"
L7 L8: library part CMP-0061053-1, "Inductor, Shielded, Composite, 4.7 uH, 13.6 A, 0.01 ohm, SMD", Manufacturer=Coilcraft, Value1="0.01 ohm", Value2=13.6A, ValueDisplayed=4.7uH
LOGO1: library part CMP-0074837-1, "IEC 61010-1 Hot Surface Warning"
Logo2: library part CMP-0074839-1
Logo3: library part CMP-0074847-1, "FCC_disclaimer"
Logo4: library part CMP-0074769-1
NT1 NT2: library part CMP-0078142-5, "Single point connection between nets.", Manufacturer=N/A
Q1: library part CMP-0080660-1, "MOSFET, N-CH, 40 V, 40 A, AEC-Q101, SON-8", Alternate Manufacturer=None, Manufacturer="Infineon Technologies", Supplier Part Number 1=IPZ40N04S5L4R8ATMA1CT-ND, Value1="0.0067 ohm", Value2="22 nC"
R1 R2: library part CMP-0017777-3, "RES, 2.20, 1%, 0.25 W, AEC-Q200 Grade 0, 1206", Manufacturer=Panasonic, PartNumber=ERJ-8RQF2R2V, Power_W=250mW, Supplier Part Number 1=P2.2RCT-ND, TempCo="200 ppm/C", Tolerance_%=1%, Value2=0.25W, Value_Code=2R20, ValueDisplayed=2.20
R3 R20: library part CMP-0086941-2, "10 mOhms ±1% 1W Chip Resistor 1206 (3216 Metric) Automotive AEC-Q200, Current Sense, Moisture Resistant Metal Element", Manufacturer=Bourns, Power_W=1W, TempCo=50ppm/°C, Tolerance_%=1%, ValueDisplayed=10m
R4 R6: library part CMP-0025963-3, "RES, 10.0, 1%, 0.063 W, AEC-Q200 Grade 0, 0402", Manufacturer=Vishay-Dale, Power_W=63mW, Supplier Part Number 1=541-10.0LCT-ND, TempCo="100 ppm/C", Tolerance_%=1%, Value2=0.063W, Value_Code=10R0, ValueDisplayed=10.0
R5: library part CMP-0027007-1, "RES, 0, 5%, 0.063 W, AEC-Q200 Grade 0, 0402", Manufacturer="KOA Speer", Power_W=63mW, Supplier Part Number 1=660-RK73Z1ETTP, TempCo=ppm/C, Tolerance_%=5%, Value2=0.063W, Value_Code=0000, ValueDisplayed=0
R7: library part CMP-0026403-2, "RES, 49.9 k, 1%, 0.063 W, AEC-Q200 Grade 0, 0402", Manufacturer=Vishay-Dale, PartNumber=CRCW040249K9FKED, Power_W=63mW, Supplier Part Number 1=541-49.9KLCT-ND, TempCo="100 ppm/C", Tolerance_%=1%, Value2=0.063W, Value_Code=49k9, ValueDisplayed=49.9k
R8: library part CMP-0025874-4, "RES, 0, 5%, 0.1 W, AEC-Q200 Grade 0, 0603", Manufacturer=Panasonic, Power_W=100mW, Supplier Part Number 1=P0.0GCT-ND, TempCo="600 ppm/C", Tolerance_%=5%, Value2=0.1W, Value_Code=0000, ValueDisplayed=0
R9: library part CMP-0026021-3, "RES, 150 k, 1%, 0.063 W, AEC-Q200 Grade 0, 0402", Manufacturer=Vishay-Dale, PartNumber=CRCW0402150KFKED, Power_W=63mW, Supplier Part Number 1=541-150KLCT-ND, TempCo="100 ppm/C", Tolerance_%=1%, Value2=0.063W, Value_Code=150k
R10: library part CMP-0026213-2, "RES, 27.4 k, 1%, 0.063 W, AEC-Q200 Grade 0, 0402", Manufacturer=Vishay-Dale, Power_W=63mW, Supplier Part Number 1=541-27.4KLCT-ND, TempCo="100 ppm/C", Tolerance_%=1%, Value2=0.063W, Value_Code=27k4, ValueDisplayed=27.4k
R11: library part CMP-0089143-1, "0 Ohms Jumper 0.1W, 1/10W Chip Resistor 0603 (1608 Metric) Automotive AEC-Q200 Thick Film", Digikey Part Number=P0.0GCT-ND, Manufacturer=Panasonic, Mouser Part Number=667-ERJ-3GEY0R00V, Operating Temperature Range="-55°C to +155°C", Power_W=100mW, TempCo=-100/+600ppm/°C, Tolerance_%=5%
R12 R13 R25 R26: library part CMP-0026750-1, "RES, 3.30 k, 1%, 0.063 W, AEC-Q200 Grade 0, 0402", Manufacturer="KOA Speer", Power_W=63mW, Supplier Part Number 1=660-RK73H1ETTP3301F, TempCo="100 ppm/C", Tolerance_%=1%, Value2=0.063W, Value_Code=3k30, ValueDisplayed=3.30k
R15 R17: library part CMP-0016749-3, "RES, 1.10, 1%, 0.25 W, AEC-Q200 Grade 0, 1206", Manufacturer=Vishay-Dale, Power_W=250mW, Supplier Part Number 1=541-1.10FFCT-ND, TempCo="100 ppm/C", Tolerance_%=1%, Value2=0.25W, Value_Code=1R10, ValueDisplayed=1.10
R16: library part CMP-0022438-1, "RES, 47.0 k, 1%, 0.1 W, AEC-Q200 Grade 0, 0603", Manufacturer=Vishay-Dale, Power_W=100mW, Supplier Part Number 1=541-47.0KHCT-ND, TempCo="100 ppm/C", Tolerance_%=1%, Value2=0.1W, Value_Code=47k0, ValueDisplayed=47.0k
R19: library part CMP-0081856-1, "RES, 0, 0%, 0.2 W, AEC-Q200 Grade 0, 0402", Manufacturer=Vishay-Dale, Power_W=200mW, Supplier Part Number 1=541-0.0YBTR-ND, Tolerance_%=0%, Value2=0.2W, Value_Code=0
R21: library part CMP-0025963-2, "RES, 10.0, 1%, 0.063 W, 0402", Manufacturer=Vishay-Dale, Power_W=63mW, Supplier Part Number 1=541-10.0LCT-ND, TempCo="100 ppm/C", Tolerance_%=1%, Value2=0.063W, Value_Code=10R0, ValueDisplayed=10.0
R22 R24: library part CMP-0026994-4, "RES, 10 k, 5%, 0.1 W, AEC-Q200 Grade 0, 0402", Manufacturer=Panasonic, Power_W=100mW, Supplier Part Number 1=P10KJCT-ND, TempCo="200 ppm/C", Tolerance_%=5%, Value2=0.1W, Value_Code=10k0, ValueDisplayed=10k
R23: library part CMP-0017851-1, "RES, 10.0, 1%, 0.25 W, 1206", Manufacturer="Yageo America", Power_W=250mW, Supplier Part Number 1=311-10.0FRCT-ND, TempCo="200 ppm/C", Tolerance_%=1%, Value2=0.25W, Value_Code=10R0, ValueDisplayed=10.0
RT1: library part CMP-0084566-1, "Thermistor, DEC0002A (X1SON-2)", Alternate Manufacturer="Texas Instruments"
SWD1: library part CMP-0054798-1, "Header, 2.54 mm, 4x1, Gold, TH", Manufacturer="Wurth Elektronik", Supplier Part Number 1=732-5317-ND
U1: library part CMP-0120176-1, "36-V, 8-A Buck-boost Converter with I2C Interface", Manufacturer="Texas Instruments", Max Supply Voltage=36V, Min Supply Voltage=3V, Nominal Supply Current=760uA, Operating Temperature Range="-40°C to +125°C", Output Voltage=0.8-22V, Switching Frequency=200-2200kHz
U2: library part CMP-0097267-2, "Automotive Single/Dual USB Type-C Power Delivery Controller with Buck-Boost Regulator", Manufacturer="Texas Instruments", Max Supply Voltage=18V, Min Supply Voltage=4.5V, Nominal Supply Current=2-60mA, Operating Temperature Range="-40°C to +150°C", Output Voltage=3-21V, Switching Frequency=300/400/450kHz
U3: library part CMP-0005262-2, "256K I2C CMOS Serial EEPROM, TSSOP-8", Manufacturer=Microchip, Supplier Part Number 1=24LC256-I/ST-ND
U4: library part CMP-0013281-4, "Low Iq Always ON Smart Diode Controller, DBV0006A (SOT-23-6)", Alternate Manufacturer="Texas Instruments", Alternate PartNumber=LM74700QDBVTQ1
U5: library part CMP-0120734-1, "Mixed-Signal Microcontroller, SOT23-8", Frequency_Fixed=24MHz, Manufacturer="Texas Instruments", Max Supply Voltage=3.6V, Min Supply Voltage=1.62V, Operating Temperature Range="-40°C to +125°C", Part Number=MSPM0C1104SDDFR

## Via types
v1: diameter 16, hole 8, Top Layer 1 to Bottom Layer, tented top, 181 vias
v2: diameter 24, hole 12, Top Layer 1 to Bottom Layer, tented top, 45 vias
v3: diameter 20, hole 10, Top Layer 1 to Bottom Layer, tented top, 34 vias
v4: diameter 28, hole 12, Top Layer 1 to Bottom Layer, 25 vias
v5: diameter 16, hole 10, Top Layer 1 to Bottom Layer, tented top, 8 vias
v6: diameter 16, hole 8, Top Layer 1 to Bottom Layer, tented both sides, 4 vias
v7: diameter 26, hole 12, Top Layer 1 to Bottom Layer, tented top, 4 vias
v8: diameter 16, hole 10, Top Layer 1 to Bottom Layer, tented both sides, 2 vias
v9: diameter 20, hole 10, Top Layer 1 to Bottom Layer, tented both sides, 1 vias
